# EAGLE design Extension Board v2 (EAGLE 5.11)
OC_FARNELL: 2065963

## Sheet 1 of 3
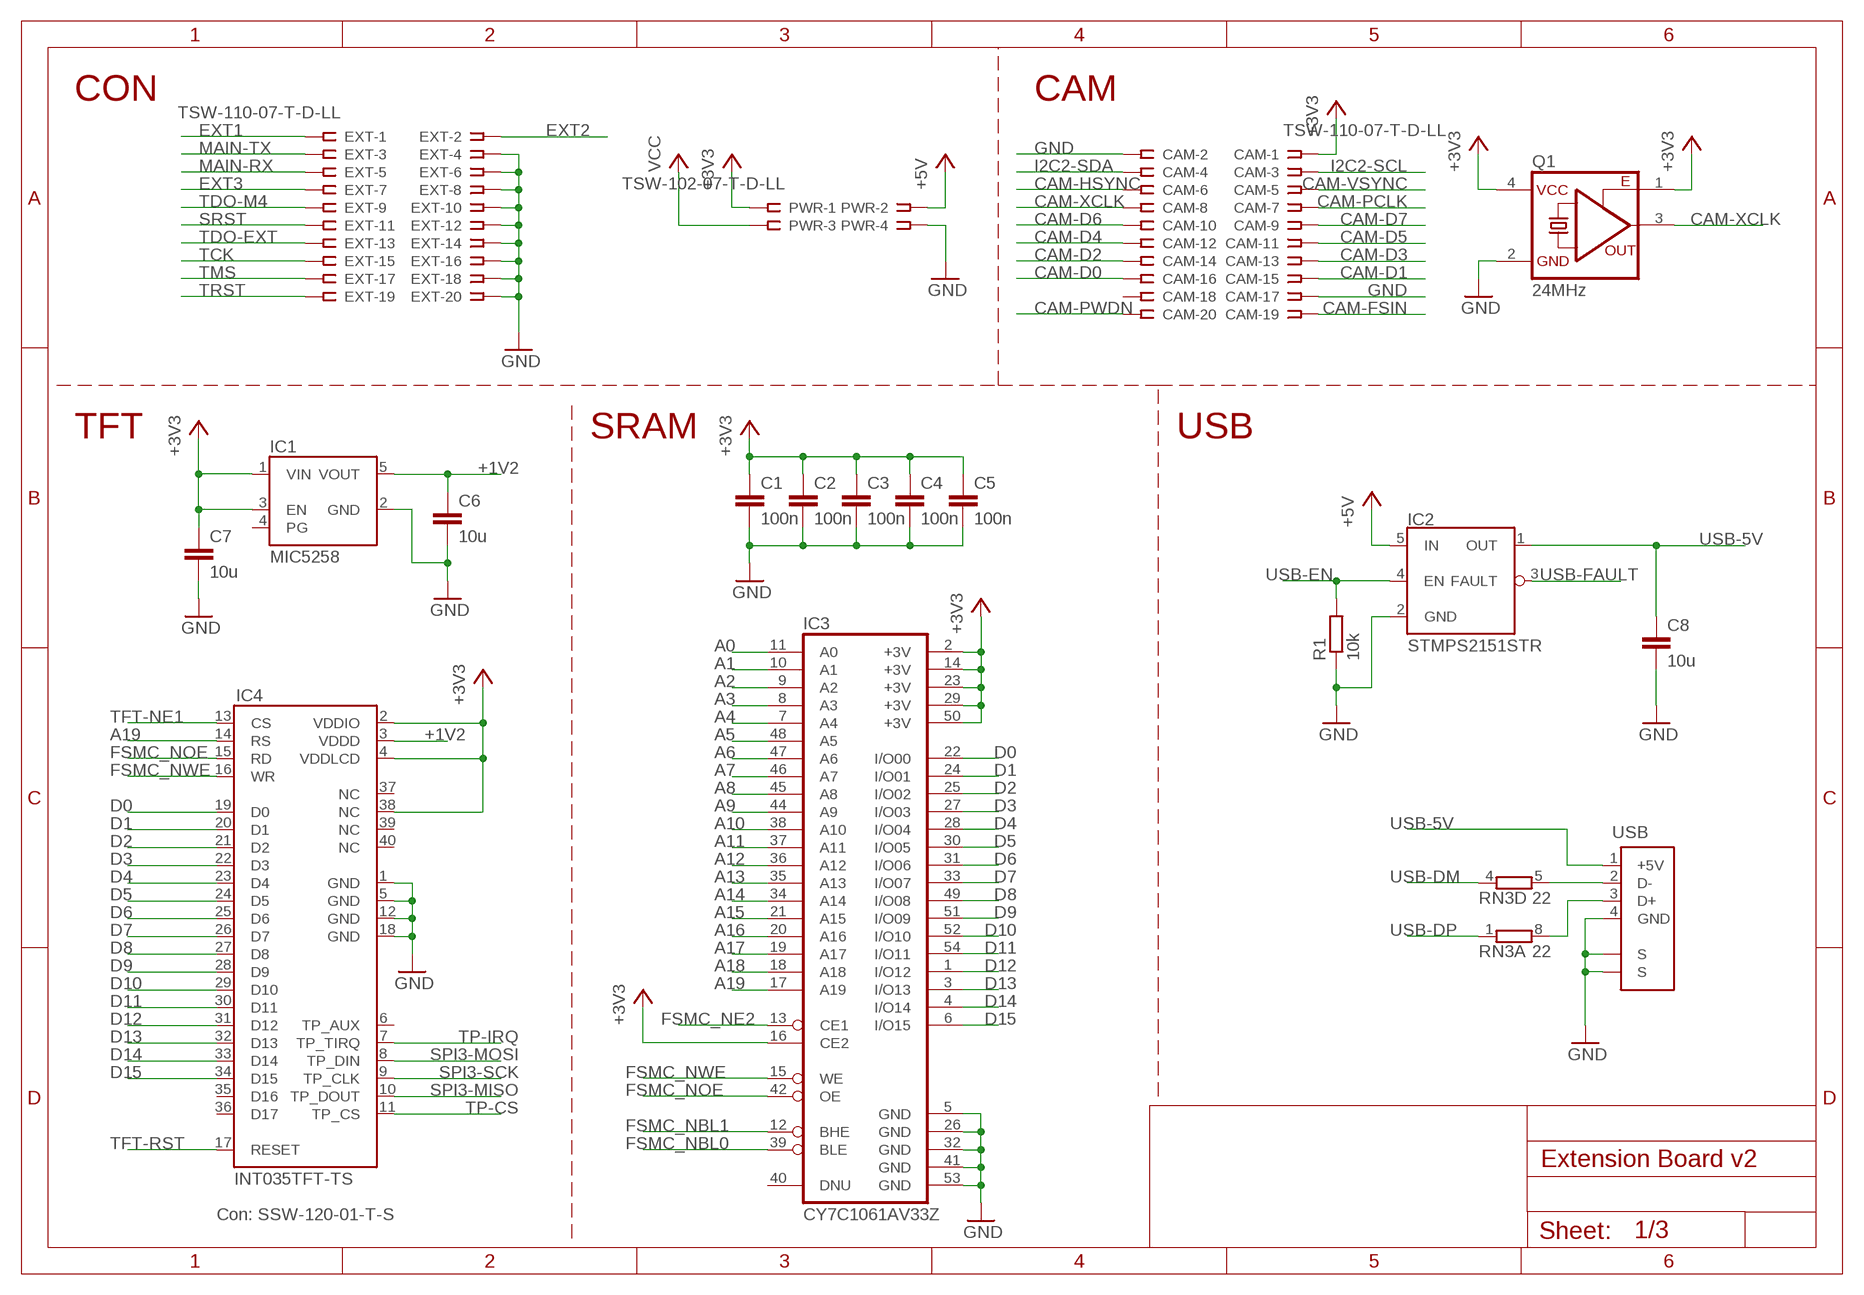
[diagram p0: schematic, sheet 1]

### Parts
C1  100n  C-EUC0805  [C0805]
C2  100n  C-EUC0805  [C0805]
C3  100n  C-EUC0805  [C0805]
C4  100n  C-EUC0805  [C0805]
C5  100n  C-EUC0805  [C0805]
C6  10u  C-EUC0805  [C0805]
C7  10u  C-EUC0805  [C0805]
C8  10u  C-EUC0805  [C0805]
CAM  TSW-110-07-T-D-LL  SSW-110-02-S-D  [SSW-110-02-S-D]
EXT  TSW-110-07-T-D-LL  SSW-110-02-S-D  [SSW-110-02-S-D]
IC1  MIC5258  LDO-EN-PG  [SOT23-5]
IC2  STMPS2151STR  [SOT23-5]
IC3  CY7C1061AV33Z  [TSOPII-54]
IC4  INT035TFT-TS  [INT035TFT-TS]
PWR  TSW-102-07-T-D-LL  SSW-102-02-S-D  [SSW-102-02-S-D]
Q1  24MHz  OSCI8W  [CRYSTAL-8W]
R1  10k  R-EU_R0805  [R0805]
RN3  22  4R-NCAY16  [CAY16]
USB  USBA  [USB-A-S-RA-TSMT]

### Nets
+1V2: C6.1 IC1.5(VOUT) IC4.3(VDDD)
+3V3: C1.1 C2.1 C3.1 C4.1 C5.1 C7.1 CAM.1 IC1.1(VIN) IC1.3(EN) IC3.2(+3V) IC3.14(+3V) IC3.16(CE2) IC3.23(+3V) IC3.29(+3V) IC3.50(+3V) IC4.2(VDDIO) IC4.4(VDDLCD) IC4.38(NC) PWR.1 Q1.1(OE) Q1.4(VCC) ; also sheet 3
+5V: IC2.5(IN) PWR.2 ; also sheet 2
A0: IC3.11(A0) ; also sheet 3
A1: IC3.10(A1) ; also sheet 3
A2: IC3.9(A2) ; also sheet 3
A3: IC3.8(A3) ; also sheet 3
A4: IC3.7(A4) ; also sheet 3
A5: IC3.48(A5) ; also sheet 3
A6: IC3.47(A6) ; also sheet 3
A7: IC3.46(A7) ; also sheet 3
A8: IC3.45(A8) ; also sheet 3
A9: IC3.44(A9) ; also sheet 3
A10: IC3.38(A10) ; also sheet 3
A11: IC3.37(A11) ; also sheet 3
A12: IC3.36(A12) ; also sheet 3
A13: IC3.35(A13) ; also sheet 3
A14: IC3.34(A14) ; also sheet 3
A15: IC3.21(A15) ; also sheet 3
A16: IC3.20(A16) ; also sheet 3
A17: IC3.19(A17) ; also sheet 3
A18: IC3.18(A18) ; also sheet 3
A19: IC3.17(A19) IC4.14(RS) ; also sheet 3
CAM-D0: CAM.16 ; also sheet 3
CAM-D1: CAM.15 ; also sheet 3
CAM-D2: CAM.14 ; also sheet 3
CAM-D3: CAM.13 ; also sheet 3
CAM-D4: CAM.12 ; also sheet 3
CAM-D5: CAM.11 ; also sheet 3
CAM-D6: CAM.10 ; also sheet 3
CAM-D7: CAM.9 ; also sheet 3
CAM-FSIN: CAM.19 ; also sheet 3
CAM-HSYNC: CAM.6 ; also sheet 3
CAM-PCLK: CAM.7 ; also sheet 3
CAM-PWDN: CAM.20 ; also sheet 3
CAM-VSYNC: CAM.5 ; also sheet 3
CAM-XCLK: CAM.8 Q1.3(FO)
D0: IC3.22(I/O00) IC4.19(D0) ; also sheet 3
D1: IC3.24(I/O01) IC4.20(D1) ; also sheet 3
D2: IC3.25(I/O02) IC4.21(D2) ; also sheet 3
D3: IC3.27(I/O03) IC4.22(D3) ; also sheet 3
D4: IC3.28(I/O04) IC4.23(D4) ; also sheet 3
D5: IC3.30(I/O05) IC4.24(D5) ; also sheet 3
D6: IC3.31(I/O06) IC4.25(D6) ; also sheet 3
D7: IC3.33(I/O07) IC4.26(D7) ; also sheet 3
D8: IC3.49(I/O08) IC4.27(D8) ; also sheet 3
D9: IC3.51(I/O09) IC4.28(D9) ; also sheet 3
D10: IC3.52(I/O10) IC4.29(D10) ; also sheet 3
D11: IC3.54(I/O11) IC4.30(D11) ; also sheet 3
D12: IC3.1(I/O12) IC4.31(D12) ; also sheet 3
D13: IC3.3(I/O13) IC4.32(D13) ; also sheet 3
D14: IC3.4(I/O14) IC4.33(D14) ; also sheet 3
D15: IC3.6(I/O15) IC4.34(D15) ; also sheet 3
EXT1: EXT.1 ; also sheet 3
EXT2: EXT.2 ; also sheet 3
EXT3: EXT.7 ; also sheet 3
FSMC_NBL0: IC3.39(BLE) ; also sheet 3
FSMC_NBL1: IC3.12(BHE) ; also sheet 3
FSMC_NE2: IC3.13(CE1) ; also sheet 3
FSMC_NOE: IC3.42(OE) IC4.15(RD) ; also sheet 3
FSMC_NWE: IC3.15(WE) IC4.16(WR) ; also sheet 3
GND: C1.2 C2.2 C3.2 C4.2 C5.2 C6.2 C7.2 C8.2 CAM.2 CAM.17 EXT.4 EXT.6 EXT.8 EXT.10 EXT.12 EXT.14 EXT.16 EXT.18 EXT.20 IC1.2(GND) IC2.2(GND) IC3.5(GND) IC3.26(GND) IC3.32(GND) IC3.41(GND) IC3.53(GND) IC4.1(GND) IC4.5(GND) IC4.12(GND) IC4.18(GND) PWR.4 Q1.2(GND) R1.1 USB.4(GND) USB.SHIELD@1(S) USB.SHIELD@2(S) ; also sheet 2,3
I2C2-SCL: CAM.3 ; also sheet 3
I2C2-SDA: CAM.4 ; also sheet 3
MAIN-RX: EXT.5 ; also sheet 3
MAIN-TX: EXT.3 ; also sheet 3
N$2: RN3.5 USB.2(D-)
N$3: RN3.8 USB.3(D+)
SPI3-MISO: IC4.10(TP_DOUT) ; also sheet 3
SPI3-MOSI: IC4.8(TP_DIN) ; also sheet 2,3
SPI3-SCK: IC4.9(TP_CLK) ; also sheet 2,3
SRST: EXT.11 ; also sheet 3
TCK: EXT.15 ; also sheet 3
TDO-EXT: EXT.13 ; also sheet 3
TDO-M4: EXT.9 ; also sheet 3
TFT-NE1: IC4.13(CS) ; also sheet 3
TFT-RST: IC4.17(RESET) ; also sheet 3
TMS: EXT.17 ; also sheet 3
TP-CS: IC4.11(TP_CS) ; also sheet 3
TP-IRQ: IC4.7(TP_TIRQ) ; also sheet 3
TRST: EXT.19 ; also sheet 3
USB-5V: C8.1 IC2.1(OUT) USB.1(+5V)
USB-DM: RN3.4 ; also sheet 3
USB-DP: RN3.1 ; also sheet 3
USB-EN: IC2.4(EN) R1.2 ; also sheet 3
USB-FAULT: IC2.3(FAULT) ; also sheet 3
VCC: PWR.3
Unconnected: CAM.18 IC1.4(PG) IC3.40(DNU) IC4.6(TP_AUX) IC4.35(D16) IC4.36(D17) IC4.37(NC) IC4.39(NC) IC4.40(NC) RN3.2 RN3.3 RN3.6 RN3.7

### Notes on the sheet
- CON | CAM
- TFT | SRAM | USB
- Con: SSW-120-01-T-S

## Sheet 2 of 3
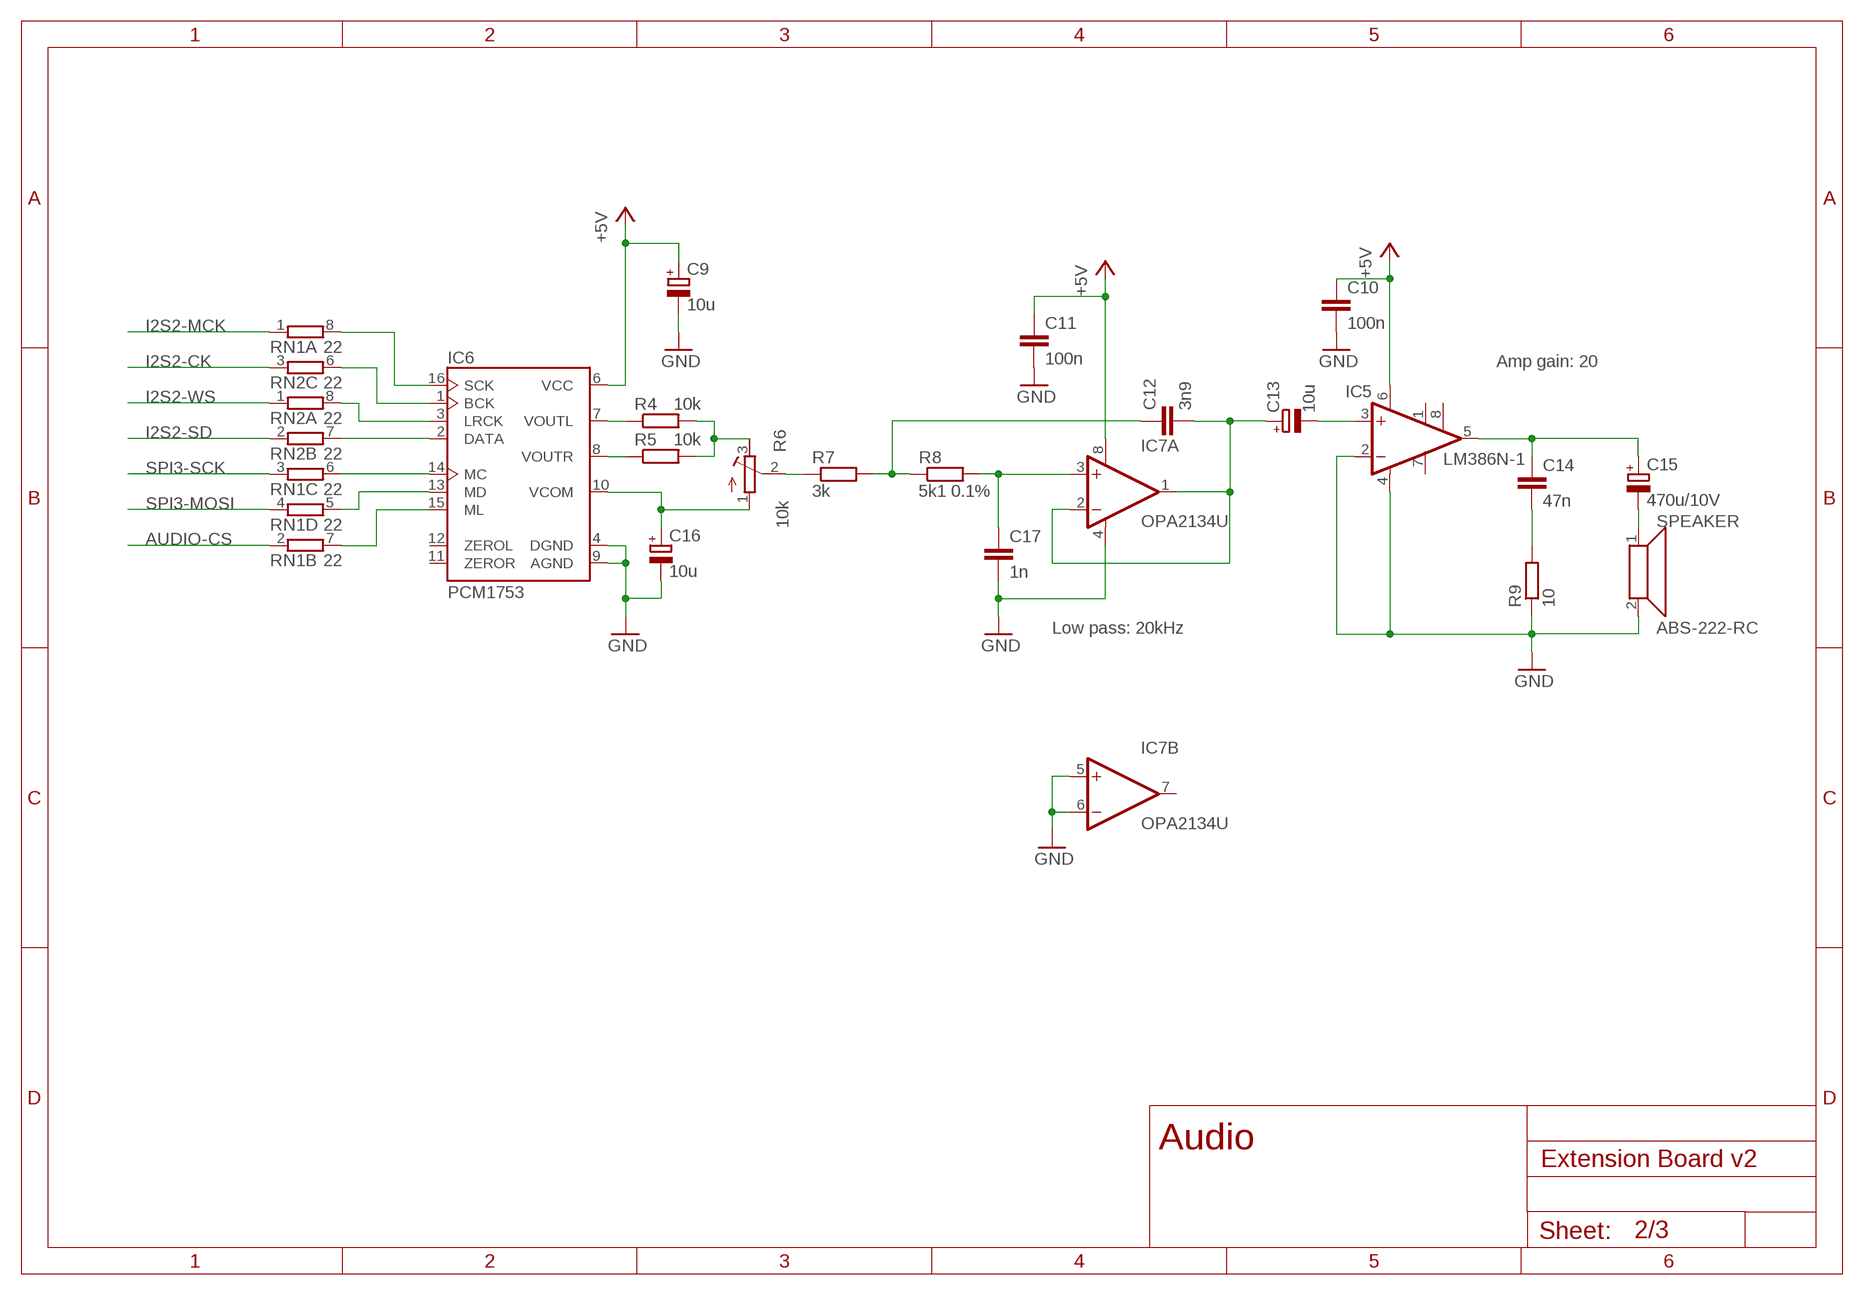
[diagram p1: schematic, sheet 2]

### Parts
C9  10u  CPOL-EUC  [PANASONIC_C]
C10  100n  C-EUC0805  [C0805]
C11  100n  C-EUC0805  [C0805]
C12  3n9  C-EUC0805  [C0805]
C13  10u  CPOL-EUC  [PANASONIC_C]
C14  47n  C-EUC0805  [C0805]
C15  470u/10V  CPOL-EUD  [PANASONIC_D]
C16  10u  CPOL-EUC  [PANASONIC_C]
C17  1n  C-EUC0805  [C0805]
IC5  LM386N-1  [DIL08]
IC6  PCM1753  [SSOP16]
IC7  OPA2134U  [SO08]
R4  10k  R-EU_R0805  [R0805]
R5  10k  R-EU_R0805  [R0805]
R6  10k  R-TRIMM64P  [RTRIM64P]
R7  3k  R-EU_R0805  [R0805]
R8  5k1 0.1%  R-EU_R0805  [R0805]
R9  10  R-EU_R0805  [R0805]
RN1  22  4R-NCAY16  [CAY16]
RN2  22  4R-NCAY16  [CAY16]
SPEAKER  ABS-222-RC  SPEAKERB  [ABS-222]

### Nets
+5V: C9.+ C10.1 C11.1 IC5.6(VS) IC6.6(VCC) IC7.8(A:V+) ; also sheet 1
AUDIO-CS: RN1.2 ; also sheet 3
GND: C9.- C10.2 C11.2 C16.- C17.2 IC5.2(-IN) IC5.4(GND) IC6.4(DGND) IC6.9(AGND) IC7.4(A:V-) IC7.5(B:+IN) IC7.6(B:-IN) R9.1 SPEAKER.2 ; also sheet 1,3
I2S2-CK: RN2.3 ; also sheet 3
I2S2-MCK: RN1.1 ; also sheet 3
I2S2-SD: RN2.2 ; also sheet 3
I2S2-WS: RN2.1 ; also sheet 3
N$1: R6.2(S) R7.1
N$4: IC6.2(DATA) RN2.7
N$6: IC6.3(LRCK) RN2.8
N$7: IC6.1(BCK) RN2.6
N$8: IC6.16(SCK) RN1.8
N$9: C14.1 C15.+ IC5.5(OUT)
N$10: C14.2 R9.2
N$11: C15.- SPEAKER.1
N$13: IC6.14(MC) RN1.6
N$14: IC6.13(MD) RN1.5
N$15: IC6.15(ML) RN1.7
N$16: IC6.7(VOUTL) R4.1
N$17: C12.1 R7.2 R8.1
N$19: C13.- IC5.3(+IN)
N$21: C16.+ IC6.10(VCOM) R6.1(E)
N$22: C17.1 IC7.3(A:+IN) R8.2
N$24: C12.2 C13.+ IC7.1(A:OUT) IC7.2(A:-IN)
N$25: IC6.8(VOUTR) R5.1
N$37: R4.2 R5.2 R6.3(A)
SPI3-MOSI: RN1.4 ; also sheet 1,3
SPI3-SCK: RN1.3 ; also sheet 1,3
Unconnected: IC5.1(GAIN) IC5.7(BYPASS) IC5.8(GAIN) IC6.11(ZEROR) IC6.12(ZEROL) IC7.7(B:OUT) RN2.4 RN2.5

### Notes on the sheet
- Amp gain: 20
- Low pass: 20kHz
- Audio

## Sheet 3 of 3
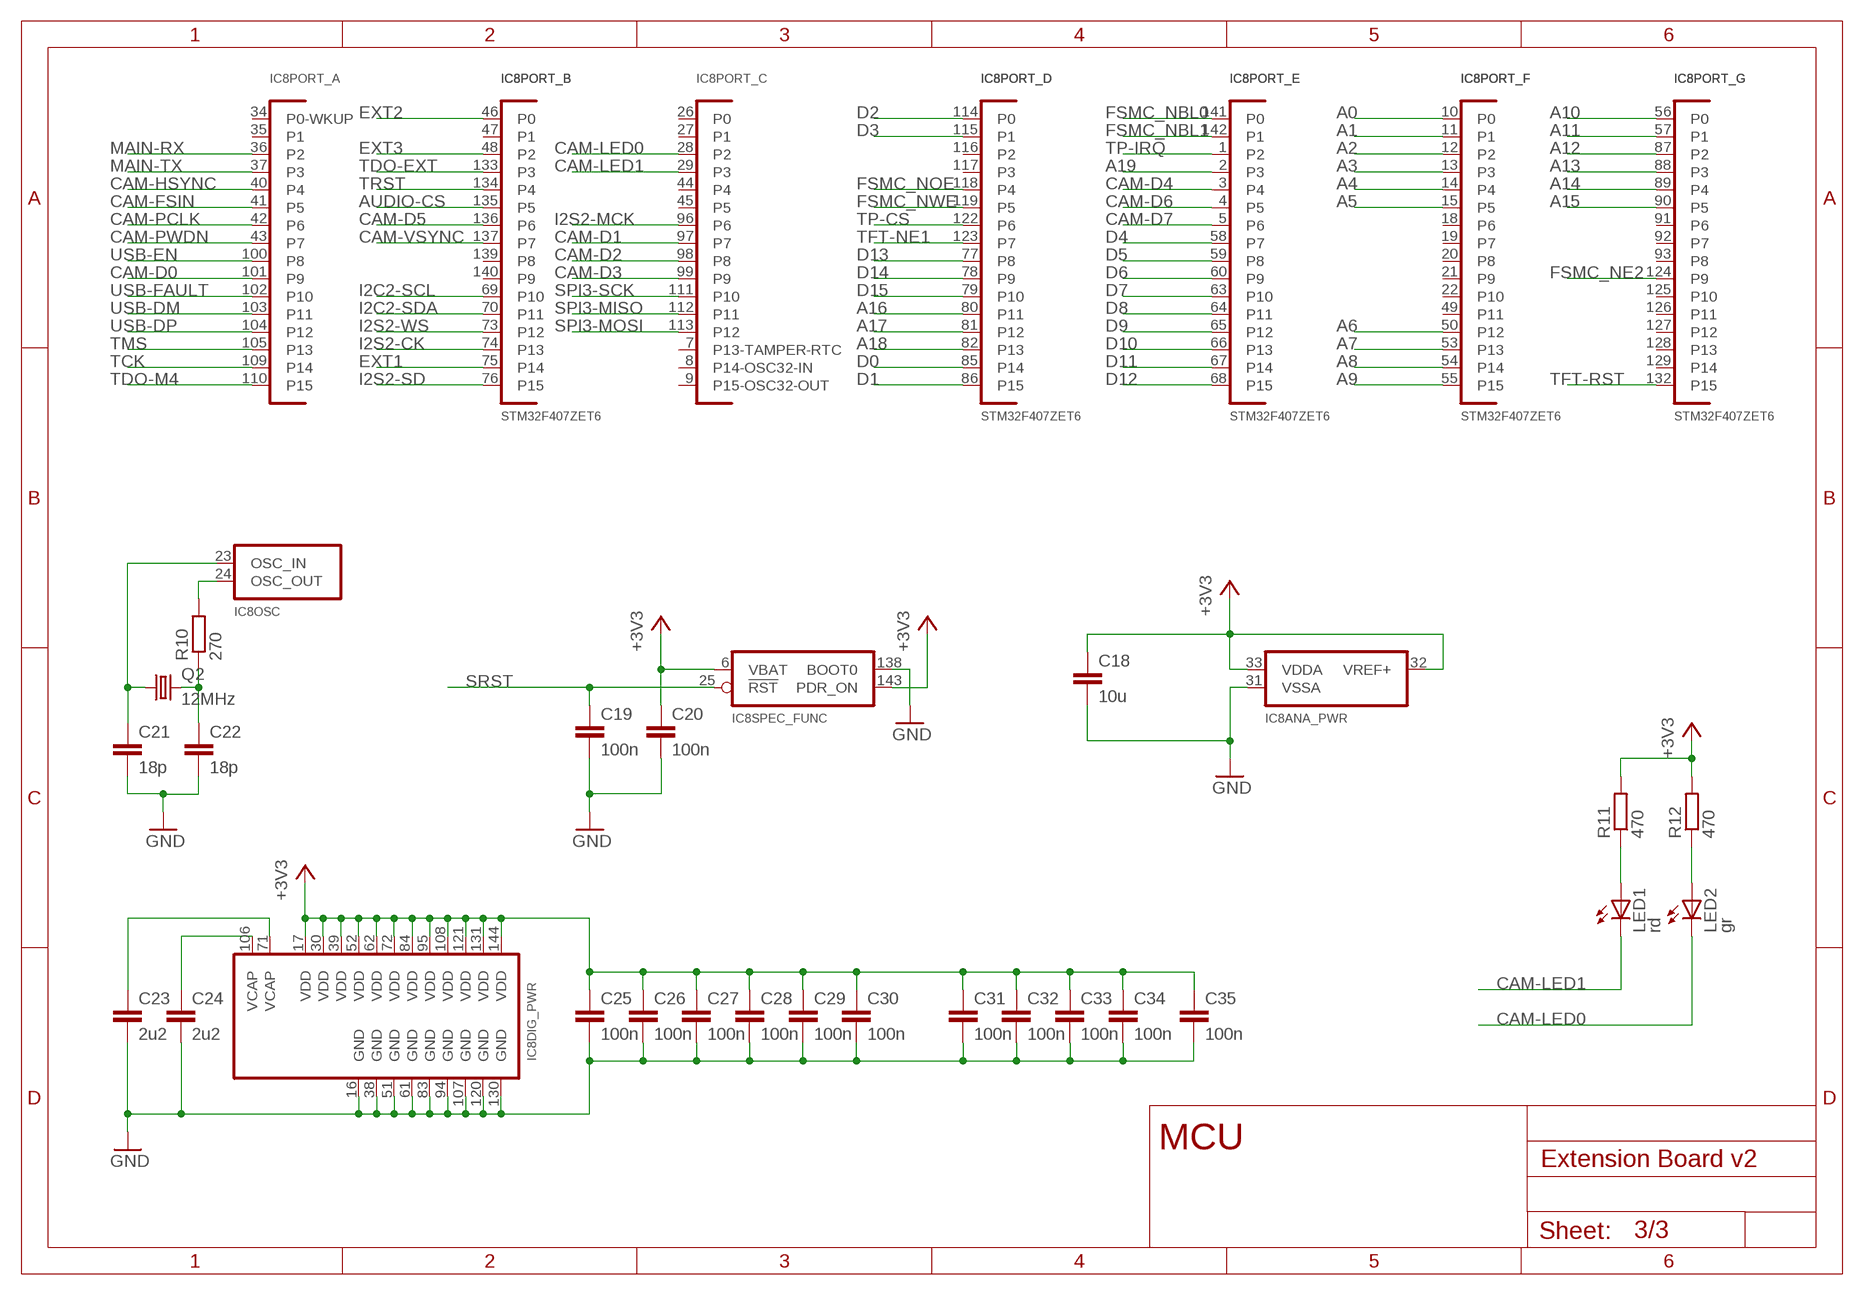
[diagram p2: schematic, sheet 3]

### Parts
C18  10u  C-EUC0805  [C0805]
C19  100n  C-EUC0805  [C0805]
C20  100n  C-EUC0805  [C0805]
C21  18p  C-EUC0805  [C0805]
C22  18p  C-EUC0805  [C0805]
C23  2u2  C-EUC0805  [C0805]
C24  2u2  C-EUC0805  [C0805]
C25  100n  C-EUC0805  [C0805]
C26  100n  C-EUC0805  [C0805]
C27  100n  C-EUC0805  [C0805]
C28  100n  C-EUC0805  [C0805]
C29  100n  C-EUC0805  [C0805]
C30  100n  C-EUC0805  [C0805]
C31  100n  C-EUC0805  [C0805]
C32  100n  C-EUC0805  [C0805]
C33  100n  C-EUC0805  [C0805]
C34  100n  C-EUC0805  [C0805]
C35  100n  C-EUC0805  [C0805]
IC8  STM32F407ZET6  STM32F40_Z  [SQFP-S-20X20-144]
LED1  rd  LEDCHIP-LED0805  [CHIP-LED0805]
LED2  gr  LEDCHIP-LED0805  [CHIP-LED0805]
Q2  12MHz  CRYSTAL7A  [CRYSTAL-7A]
R10  270  R-EU_R0805  [R0805]
R11  470  R-EU_R0805  [R0805]
R12  470  R-EU_R0805  [R0805]

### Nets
+3V3: C18.1 C20.1 C25.1 C26.1 C27.1 C28.1 C29.1 C30.1 C31.1 C32.1 C33.1 C34.1 C35.1 IC8.6(SPEC_FUNC:VBAT) IC8.17(DIG_PWR:VDD) IC8.30(DIG_PWR:VDD) IC8.32(ANA_PWR:VREF+) IC8.33(ANA_PWR:VDDA) IC8.39(DIG_PWR:VDD) IC8.52(DIG_PWR:VDD) IC8.62(DIG_PWR:VDD) IC8.72(DIG_PWR:VDD) IC8.84(DIG_PWR:VDD) IC8.95(DIG_PWR:VDD) IC8.108(DIG_PWR:VDD) IC8.121(DIG_PWR:VDD) IC8.131(DIG_PWR:VDD) IC8.143(SPEC_FUNC:PDR_ON) IC8.144(DIG_PWR:VDD) R11.2 R12.2 ; also sheet 1
A0: IC8.10(PORT_F:P0) ; also sheet 1
A1: IC8.11(PORT_F:P1) ; also sheet 1
A2: IC8.12(PORT_F:P2) ; also sheet 1
A3: IC8.13(PORT_F:P3) ; also sheet 1
A4: IC8.14(PORT_F:P4) ; also sheet 1
A5: IC8.15(PORT_F:P5) ; also sheet 1
A6: IC8.50(PORT_F:P12) ; also sheet 1
A7: IC8.53(PORT_F:P13) ; also sheet 1
A8: IC8.54(PORT_F:P14) ; also sheet 1
A9: IC8.55(PORT_F:P15) ; also sheet 1
A10: IC8.56(PORT_G:P0) ; also sheet 1
A11: IC8.57(PORT_G:P1) ; also sheet 1
A12: IC8.87(PORT_G:P2) ; also sheet 1
A13: IC8.88(PORT_G:P3) ; also sheet 1
A14: IC8.89(PORT_G:P4) ; also sheet 1
A15: IC8.90(PORT_G:P5) ; also sheet 1
A16: IC8.80(PORT_D:P11) ; also sheet 1
A17: IC8.81(PORT_D:P12) ; also sheet 1
A18: IC8.82(PORT_D:P13) ; also sheet 1
A19: IC8.2(PORT_E:P3) ; also sheet 1
AUDIO-CS: IC8.135(PORT_B:P5) ; also sheet 2
CAM-D0: IC8.101(PORT_A:P9) ; also sheet 1
CAM-D1: IC8.97(PORT_C:P7) ; also sheet 1
CAM-D2: IC8.98(PORT_C:P8) ; also sheet 1
CAM-D3: IC8.99(PORT_C:P9) ; also sheet 1
CAM-D4: IC8.3(PORT_E:P4) ; also sheet 1
CAM-D5: IC8.136(PORT_B:P6) ; also sheet 1
CAM-D6: IC8.4(PORT_E:P5) ; also sheet 1
CAM-D7: IC8.5(PORT_E:P6) ; also sheet 1
CAM-FSIN: IC8.41(PORT_A:P5) ; also sheet 1
CAM-HSYNC: IC8.40(PORT_A:P4) ; also sheet 1
CAM-LED0: IC8.28(PORT_C:P2) LED2.C
CAM-LED1: IC8.29(PORT_C:P3) LED1.C
CAM-PCLK: IC8.42(PORT_A:P6) ; also sheet 1
CAM-PWDN: IC8.43(PORT_A:P7) ; also sheet 1
CAM-VSYNC: IC8.137(PORT_B:P7) ; also sheet 1
D0: IC8.85(PORT_D:P14) ; also sheet 1
D1: IC8.86(PORT_D:P15) ; also sheet 1
D2: IC8.114(PORT_D:P0) ; also sheet 1
D3: IC8.115(PORT_D:P1) ; also sheet 1
D4: IC8.58(PORT_E:P7) ; also sheet 1
D5: IC8.59(PORT_E:P8) ; also sheet 1
D6: IC8.60(PORT_E:P9) ; also sheet 1
D7: IC8.63(PORT_E:P10) ; also sheet 1
D8: IC8.64(PORT_E:P11) ; also sheet 1
D9: IC8.65(PORT_E:P12) ; also sheet 1
D10: IC8.66(PORT_E:P13) ; also sheet 1
D11: IC8.67(PORT_E:P14) ; also sheet 1
D12: IC8.68(PORT_E:P15) ; also sheet 1
D13: IC8.77(PORT_D:P8) ; also sheet 1
D14: IC8.78(PORT_D:P9) ; also sheet 1
D15: IC8.79(PORT_D:P10) ; also sheet 1
EXT1: IC8.75(PORT_B:P14) ; also sheet 1
EXT2: IC8.46(PORT_B:P0) ; also sheet 1
EXT3: IC8.48(PORT_B:P2) ; also sheet 1
FSMC_NBL0: IC8.141(PORT_E:P0) ; also sheet 1
FSMC_NBL1: IC8.142(PORT_E:P1) ; also sheet 1
FSMC_NE2: IC8.124(PORT_G:P9) ; also sheet 1
FSMC_NOE: IC8.118(PORT_D:P4) ; also sheet 1
FSMC_NWE: IC8.119(PORT_D:P5) ; also sheet 1
GND: C18.2 C19.2 C20.2 C21.2 C22.2 C23.2 C24.2 C25.2 C26.2 C27.2 C28.2 C29.2 C30.2 C31.2 C32.2 C33.2 C34.2 C35.2 IC8.16(DIG_PWR:GND) IC8.31(ANA_PWR:VSSA) IC8.38(DIG_PWR:GND) IC8.51(DIG_PWR:GND) IC8.61(DIG_PWR:GND) IC8.83(DIG_PWR:GND) IC8.94(DIG_PWR:GND) IC8.107(DIG_PWR:GND) IC8.120(DIG_PWR:GND) IC8.130(DIG_PWR:GND) IC8.138(SPEC_FUNC:BOOT0) ; also sheet 1,2
I2C2-SCL: IC8.69(PORT_B:P10) ; also sheet 1
I2C2-SDA: IC8.70(PORT_B:P11) ; also sheet 1
I2S2-CK: IC8.74(PORT_B:P13) ; also sheet 2
I2S2-MCK: IC8.96(PORT_C:P6) ; also sheet 2
I2S2-SD: IC8.76(PORT_B:P15) ; also sheet 2
I2S2-WS: IC8.73(PORT_B:P12) ; also sheet 2
MAIN-RX: IC8.36(PORT_A:P2) ; also sheet 1
MAIN-TX: IC8.37(PORT_A:P3) ; also sheet 1
N$27: C24.1 IC8.106(DIG_PWR:VCAP)
N$28: C23.1 IC8.71(DIG_PWR:VCAP)
N$31: IC8.24(OSC:OSC_OUT) R10.2
N$32: C21.1 IC8.23(OSC:OSC_IN) Q2.1
N$33: C22.1 Q2.2 R10.1
N$35: LED2.A R12.1
N$36: LED1.A R11.1
SPI3-MISO: IC8.112(PORT_C:P11) ; also sheet 1
SPI3-MOSI: IC8.113(PORT_C:P12) ; also sheet 1,2
SPI3-SCK: IC8.111(PORT_C:P10) ; also sheet 1,2
SRST: C19.1 IC8.25(SPEC_FUNC:!RST) ; also sheet 1
TCK: IC8.109(PORT_A:P14) ; also sheet 1
TDO-EXT: IC8.133(PORT_B:P3) ; also sheet 1
TDO-M4: IC8.110(PORT_A:P15) ; also sheet 1
TFT-NE1: IC8.123(PORT_D:P7) ; also sheet 1
TFT-RST: IC8.132(PORT_G:P15) ; also sheet 1
TMS: IC8.105(PORT_A:P13) ; also sheet 1
TP-CS: IC8.122(PORT_D:P6) ; also sheet 1
TP-IRQ: IC8.1(PORT_E:P2) ; also sheet 1
TRST: IC8.134(PORT_B:P4) ; also sheet 1
USB-DM: IC8.103(PORT_A:P11) ; also sheet 1
USB-DP: IC8.104(PORT_A:P12) ; also sheet 1
USB-EN: IC8.100(PORT_A:P8) ; also sheet 1
USB-FAULT: IC8.102(PORT_A:P10) ; also sheet 1
Unconnected: IC8.7(PORT_C:P13-TAMPER-RTC) IC8.8(PORT_C:P14-OSC32-IN) IC8.9(PORT_C:P15-OSC32-OUT) IC8.18(PORT_F:P6) IC8.19(PORT_F:P7) IC8.20(PORT_F:P8) IC8.21(PORT_F:P9) IC8.22(PORT_F:P10) IC8.26(PORT_C:P0) IC8.27(PORT_C:P1) IC8.34(PORT_A:P0-WKUP) IC8.35(PORT_A:P1) IC8.44(PORT_C:P4) IC8.45(PORT_C:P5) IC8.47(PORT_B:P1) IC8.49(PORT_F:P11) IC8.91(PORT_G:P6) IC8.92(PORT_G:P7) IC8.93(PORT_G:P8) IC8.116(PORT_D:P2) IC8.117(PORT_D:P3) IC8.125(PORT_G:P10) IC8.126(PORT_G:P11) IC8.127(PORT_G:P12) IC8.128(PORT_G:P13) IC8.129(PORT_G:P14) IC8.139(PORT_B:P8) IC8.140(PORT_B:P9)

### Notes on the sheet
- MCU

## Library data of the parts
C1-C8 C10-C12 C14 C17-C35 = rcl:C-EU: CAPACITOR, European symbol
C9 C13 C15 C16 = rcl:CPOL-EU: POLARIZED CAPACITOR, European symbol
CAM EXT = con-samtec:SSW-110-02-S-D: THROUGH-HOLE .025" SQ POST SOCKET Source: Samtec SSW.pdf; MPN: SSW-110-02-S-D; OC_FARNELL: unknown; OC_NEWARK: 11P9480
IC1 = Marvin:LDO-EN-PG
IC2 = Marvin:STMPS21
IC3 = Marvin:CY7C1061AV33Z: 1M x 16 Static RAM Source: CYPRESS cy7c1061av33_8.pdf
IC4 = Marvin:INT035TFT-TS: Displaytech INT035TFT-TS QVGA full color display with touch-screen
IC5 = linear:LM386?-*: Low Voltage Audio Power Amplifier Source: http://cache.national.com/ds/LM/LM386.pdf
IC6 = Marvin:PCM1753
IC7 = burr-brown:OPA2134: Operational Amplifier; MF: TEXAS INSTRUMENTS; MPN: OPA2134UA; OC_FARNELL: 1206935; OC_NEWARK: 35C1847
IC8 = Marvin:STM32F40_Z: 168 MHz, 192KB RAM, 1024 KB Flash
LED1 LED2 = led:LED: LED
PWR = con-samtec:SSW-102-02-S-D: THROUGH-HOLE .025" SQ POST SOCKET Source: Samtec SSW.pdf; MPN: SSW-102-02-S-D; OC_FARNELL: unknown; OC_NEWARK: 11P9349
Q1 = Marvin:OSCI
Q2 = Marvin:CRYSTAL
R1 R4 R5 R7-R12 = rcl:R-EU_: RESISTOR, European symbol
R6 = rcl:R-TRIMM: Trimm resistor
RN1-RN3 = resistor-dil:4R-N: Array Chip Resistor Source: RS Component / Phycomp; OC_FARNELL: unknown; OC_NEWARK: unknown
SPEAKER = Marvin:SPEAKER
USB = Marvin:USBA: Multicomp connector Farnell: 2112370

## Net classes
0 default: width 0.152 mm, clearance 0.152 mm

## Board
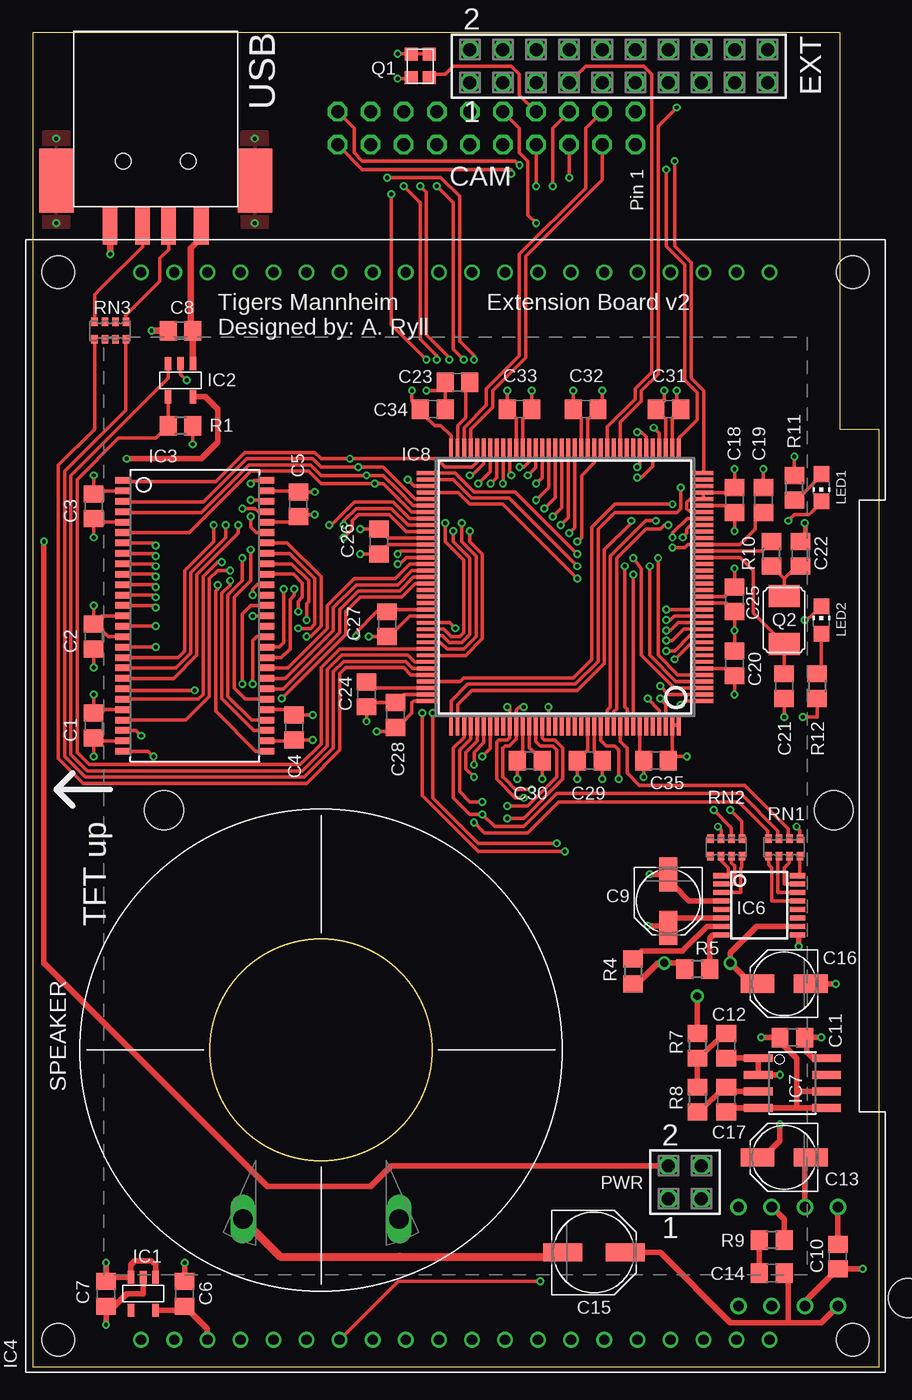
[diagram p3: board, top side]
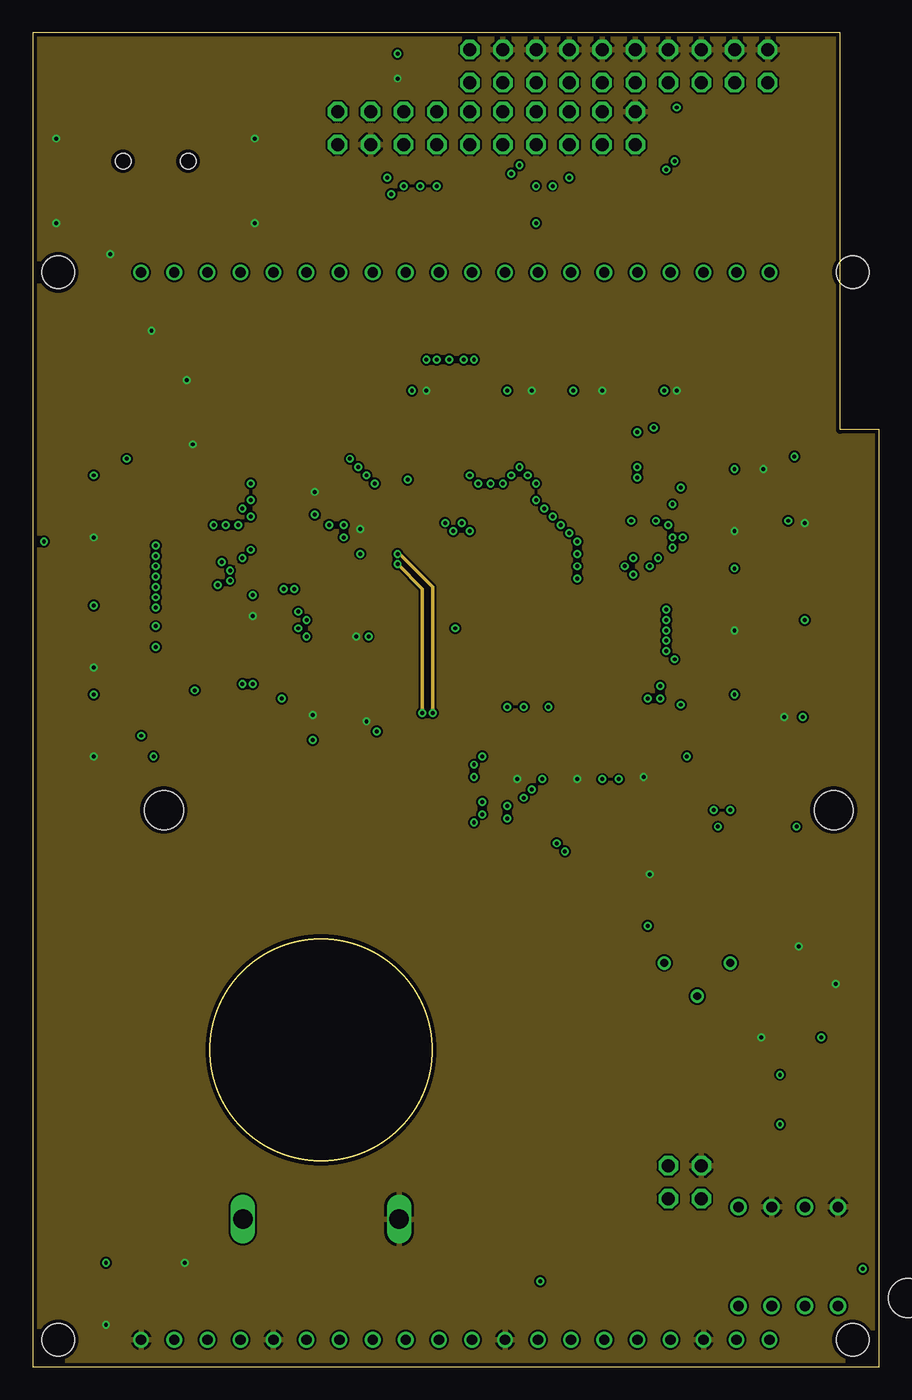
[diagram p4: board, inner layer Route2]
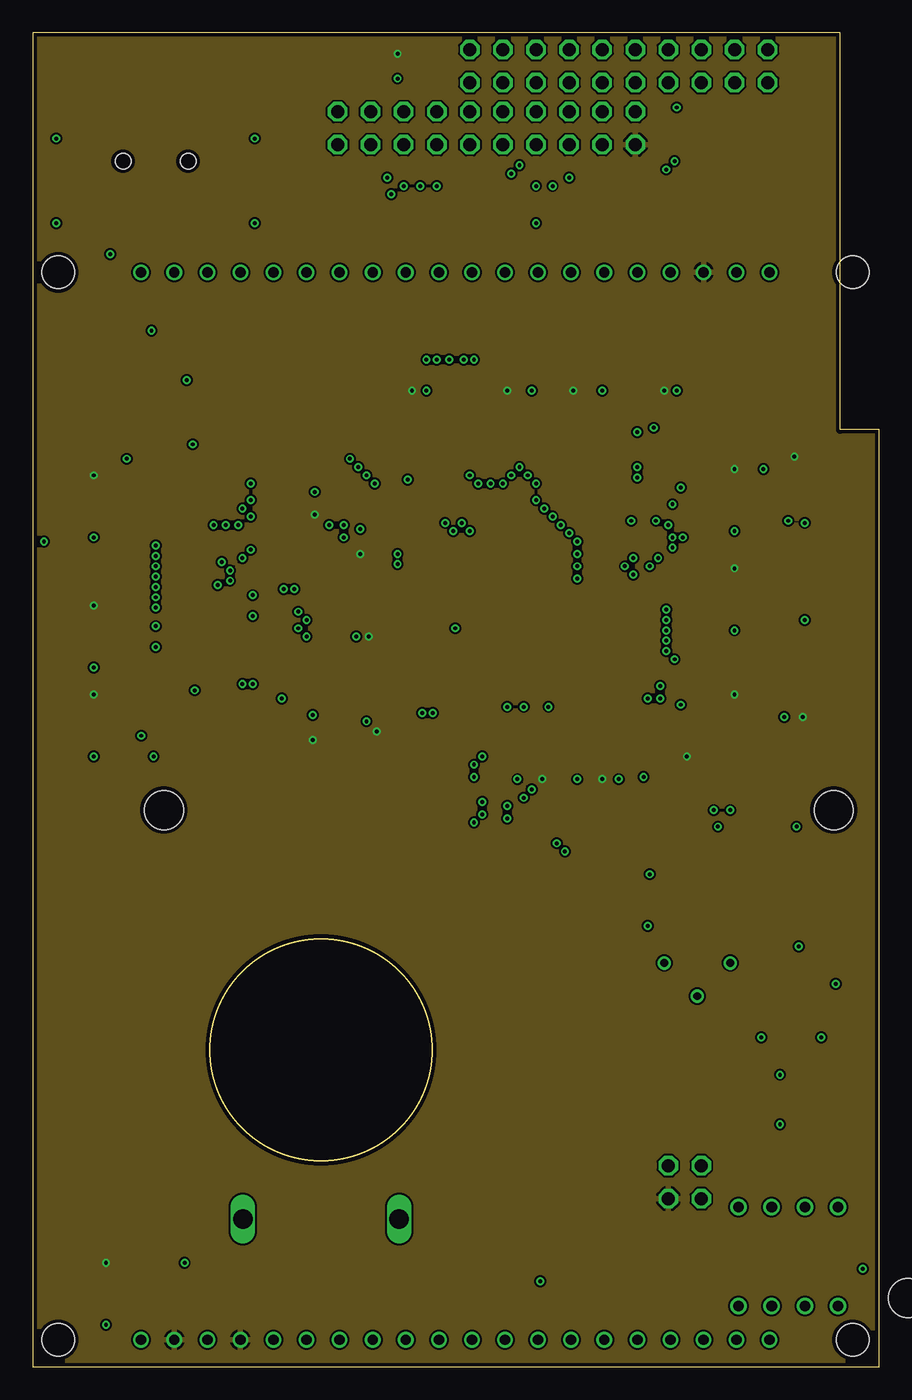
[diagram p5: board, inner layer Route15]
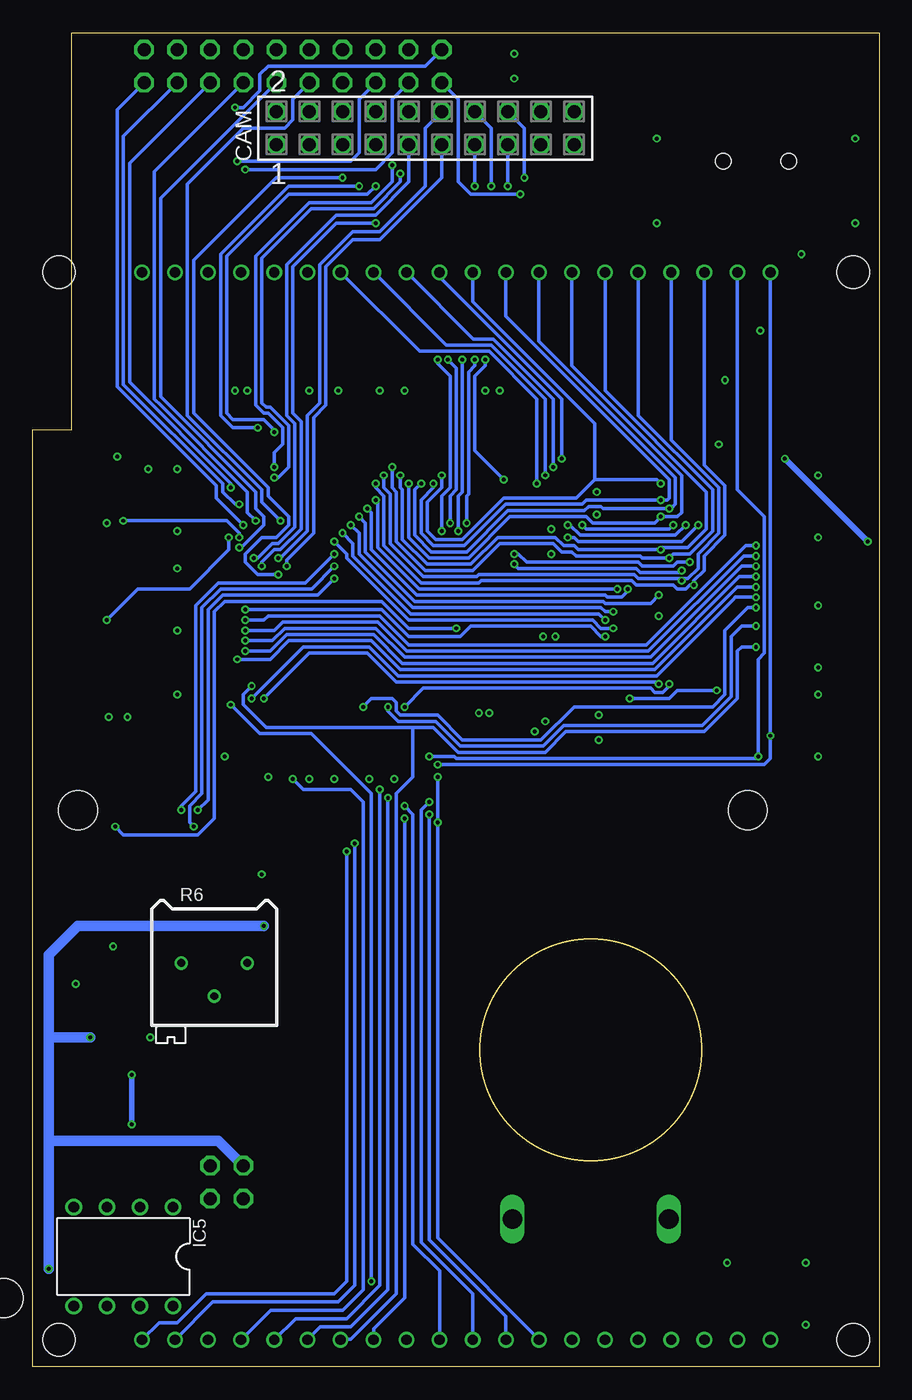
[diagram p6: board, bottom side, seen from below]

Size 65 x 102.5 mm. Coordinates in mm from the lower left corner, seen from the top.
Outline: 0,0 65,0 65,72 62,72 62,102.5 0,102.5 0,0
Copper layers (1+2*15+16): Top 0.035mm / dielectric 0.38mm / Route2 0.035mm / dielectric 0.71mm / Route15 0.035mm / dielectric 0.38mm / Bottom 0.035mm
Design rules "PCB-POOL Standard_ML4": minimum track width 0.15mm, minimum drill 0.3mm, track to track 0.15mm, track to pad 0.15mm, pad to pad 0.15mm, via to via 0.15mm, smd to smd 0.15mm, copper to edge 0.3mm, drill to drill 0.2mm, minimum pad ring 0.2mm, minimum via ring 0.15mm, stop-mask expansion 0.075mm, vias tented up to drill 0mil, thermal gap 0.2mm
Holes 3 mm at 61.52,42.77 10.09,42.77 67.23,5.3
tKeepout: area 7.1,39.8 to 13.1,45.8

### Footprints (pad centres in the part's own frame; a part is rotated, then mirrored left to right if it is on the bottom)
C0805 = smd 1.3 x 1.5: 1 -0.95,0; 2 0.95,0
PANASONIC_C = smd 2.6 x 1.4: + 2.05,0; - -2.05,0
PANASONIC_D = smd 3 x 1.4: + 2.4,0; - -2.4,0
SSW-110-02-S-D = drill 1 pad 1.5 octagon: 1 -11.43,-1.27; 2 -11.43,1.27; 3 -8.89,-1.27; 4 -8.89,1.27; 5 -6.35,-1.27; 6 -6.35,1.27; 7 -3.81,-1.27; 8 -3.81,1.27; 9 -1.27,-1.27; 10 -1.27,1.27; 11 1.27,-1.27; 12 1.27,1.27; 13 3.81,-1.27; 14 3.81,1.27; 15 6.35,-1.27; 16 6.35,1.27; 17 8.89,-1.27; 18 8.89,1.27; 19 11.43,-1.27; 20 11.43,1.27
SOT23-5 = smd 1.016 x 0.508: 1 -1.27,0.953; 2 -1.27,0; 3 -1.27,-0.953; 4 1.27,-0.953; 5 1.27,0.953
TSOPII-54 = smd 0.5 x 1.2: 1 -10.4,-5.502; 2 -9.6,-5.502; 3 -8.8,-5.502; 4 -8,-5.502; 5 -7.2,-5.502; 6 -6.4,-5.502; 7 -5.6,-5.502; 8 -4.8,-5.502; 9 -4,-5.502; 10 -3.2,-5.502; 11 -2.4,-5.502; 12 -1.6,-5.502; 13 -0.8,-5.502; 14 0,-5.502; 15 0.8,-5.502; 16 1.6,-5.502; 17 2.4,-5.502; 18 3.2,-5.502; 19 4,-5.502; 20 4.8,-5.502; 21 5.6,-5.502; 22 6.4,-5.502; 23 7.2,-5.502; 24 8,-5.502; 25 8.8,-5.502; 26 9.6,-5.502; 27 10.4,-5.502; 28 10.4,5.502; 29 9.6,5.502; 30 8.8,5.502; 31 8,5.502; 32 7.2,5.502; 33 6.4,5.502; 34 5.6,5.502; 35 4.8,5.502; 36 4,5.502; 37 3.2,5.502; 38 2.4,5.502; 39 1.6,5.502; 40 0.8,5.502; 41 0,5.502; 42 -0.8,5.502; 43 -1.6,5.502; 44 -2.4,5.502; 45 -3.2,5.502; 46 -4,5.502; 47 -4.8,5.502; 48 -5.6,5.502; 49 -6.4,5.502; 50 -7.2,5.502; 51 -8,5.502; 52 -8.8,5.502; 53 -9.6,5.502; 54 -10.4,5.502
INT035TFT-TS = drill 0.8 round: 1 -41,24.13; 2 -41,21.59; 3 -41,19.05; 4 -41,16.51; 5 -41,13.97; 6 -41,11.43; 7 -41,8.89; 8 -41,6.35; 9 -41,3.81; 10 -41,1.27; 11 -41,-1.27; 12 -41,-3.81; 13 -41,-6.35; 14 -41,-8.89; 15 -41,-11.43; 16 -41,-13.97; 17 -41,-16.51; 18 -41,-19.05; 19 -41,-21.59; 20 -41,-24.13; 21 41,24.13; 22 41,21.59; 23 41,19.05; 24 41,16.51; 25 41,13.97; 26 41,11.43; 27 41,8.89; 28 41,6.35; 29 41,3.81; 30 41,1.27; 31 41,-1.27; 32 41,-3.81; 33 41,-6.35; 34 41,-8.89; 35 41,-11.43; 36 41,-13.97; 37 41,-16.51; 38 41,-19.05; 39 41,-21.59; 40 41,-24.13 | hole 2.5: -41,30.5; 41,30.5; 41,-30.5; -41,-30.5
DIL08 = drill 0.813 pad 1.27 round: 1 -3.81,-3.81; 2 -1.27,-3.81; 3 1.27,-3.81; 4 3.81,-3.81; 5 3.81,3.81; 6 1.27,3.81; 7 -1.27,3.81; 8 -3.81,3.81
SSOP16 = smd 0.4 x 1.2: 1 -2.275,-2.925; 2 -1.625,-2.925; 3 -0.975,-2.925; 4 -0.325,-2.925; 5 0.325,-2.925; 6 0.975,-2.925; 7 1.625,-2.925; 8 2.275,-2.925; 9 2.275,2.925; 10 1.625,2.925; 11 0.975,2.925; 12 0.325,2.925; 13 -0.325,2.925; 14 -0.975,2.925; 15 -1.625,2.925; 16 -2.275,2.925
SO08 = smd 0.61 x 2.21: 1 -1.905,-2.616; 2 -0.635,-2.616; 3 0.635,-2.616; 4 1.905,-2.616; 5 1.905,2.616; 6 0.635,2.616; 7 -0.635,2.616; 8 -1.905,2.616
SQFP-S-20X20-144 = smd 0.3 x 1.6: 1 -8.75,-10.6; 2 -8.25,-10.6; 3 -7.75,-10.6; 4 -7.25,-10.6; 5 -6.75,-10.6; 6 -6.25,-10.6; 7 -5.75,-10.6; 8 -5.25,-10.6; 9 -4.75,-10.6; 10 -4.25,-10.6; 11 -3.75,-10.6; 12 -3.25,-10.6; 13 -2.75,-10.6; 14 -2.25,-10.6; 15 -1.75,-10.6; 16 -1.25,-10.6; 17 -0.75,-10.6; 18 -0.25,-10.6; 19 0.25,-10.6; 20 0.75,-10.6; 21 1.25,-10.6; 22 1.75,-10.6; 23 2.25,-10.6; 24 2.75,-10.6; 25 3.25,-10.6; 26 3.75,-10.6; 27 4.25,-10.6; 28 4.75,-10.6; 29 5.25,-10.6; 30 5.75,-10.6; 31 6.25,-10.6; 32 6.75,-10.6; 33 7.25,-10.6; 34 7.75,-10.6; 35 8.25,-10.6; 36 8.75,-10.6; 73 8.75,10.6; 74 8.25,10.6; 75 7.75,10.6; 76 7.25,10.6; 77 6.75,10.6; 78 6.25,10.6; 79 5.75,10.6; 80 5.25,10.6; 81 4.75,10.6; 82 4.25,10.6; 83 3.75,10.6; 84 3.25,10.6; 85 2.75,10.6; 86 2.25,10.6; 87 1.75,10.6; 88 1.25,10.6; 89 0.75,10.6; 90 0.25,10.6; 91 -0.25,10.6; 92 -0.75,10.6; 93 -1.25,10.6; 94 -1.75,10.6; 95 -2.25,10.6; 96 -2.75,10.6; 97 -3.25,10.6; 98 -3.75,10.6; 99 -4.25,10.6; 100 -4.75,10.6; 101 -5.25,10.6; 102 -5.75,10.6; 103 -6.25,10.6; 104 -6.75,10.6; 105 -7.25,10.6; 106 -7.75,10.6; 107 -8.25,10.6; 108 -8.75,10.6 | smd 1.6 x 0.3: 37 10.6,-8.75; 38 10.6,-8.25; 39 10.6,-7.75; 40 10.6,-7.25; 41 10.6,-6.75; 42 10.6,-6.25; 43 10.6,-5.75; 44 10.6,-5.25; 45 10.6,-4.75; 46 10.6,-4.25; 47 10.6,-3.75; 48 10.6,-3.25; 49 10.6,-2.75; 50 10.6,-2.25; 51 10.6,-1.75; 52 10.6,-1.25; 53 10.6,-0.75; 54 10.6,-0.25; 55 10.6,0.25; 56 10.6,0.75; 57 10.6,1.25; 58 10.6,1.75; 59 10.6,2.25; 60 10.6,2.75; 61 10.6,3.25; 62 10.6,3.75; 63 10.6,4.25; 64 10.6,4.75; 65 10.6,5.25; 66 10.6,5.75; 67 10.6,6.25; 68 10.6,6.75; 69 10.6,7.25; 70 10.6,7.75; 71 10.6,8.25; 72 10.6,8.75; 109 -10.6,8.75; 110 -10.6,8.25; 111 -10.6,7.75; 112 -10.6,7.25; 113 -10.6,6.75; 114 -10.6,6.25; 115 -10.6,5.75; 116 -10.6,5.25; 117 -10.6,4.75; 118 -10.6,4.25; 119 -10.6,3.75; 120 -10.6,3.25; 121 -10.6,2.75; 122 -10.6,2.25; 123 -10.6,1.75; 124 -10.6,1.25; 125 -10.6,0.75; 126 -10.6,0.25; 127 -10.6,-0.25; 128 -10.6,-0.75; 129 -10.6,-1.25; 130 -10.6,-1.75; 131 -10.6,-2.25; 132 -10.6,-2.75; 133 -10.6,-3.25; 134 -10.6,-3.75; 135 -10.6,-4.25; 136 -10.6,-4.75; 137 -10.6,-5.25; 138 -10.6,-5.75; 139 -10.6,-6.25; 140 -10.6,-6.75; 141 -10.6,-7.25; 142 -10.6,-7.75; 143 -10.6,-8.25; 144 -10.6,-8.75
CHIP-LED0805 = smd 1.2 x 1.2: A 0,-1.05; C 0,1.05
SSW-102-02-S-D = drill 1 pad 1.5 octagon: 1 -1.27,-1.27; 2 -1.27,1.27; 3 1.27,-1.27; 4 1.27,1.27
CRYSTAL-8W = smd 1 x 1: 1 -0.9,-0.7; 2 0.9,-0.7; 3 0.9,0.7; 4 -0.9,0.7
CRYSTAL-7A = smd 1.7 x 2.4: 1 -1.85,0; 2 1.85,0
R0805 = smd 1.3 x 1.5: 1 -0.95,0; 2 0.95,0
RTRIM64P = drill 0.61 round: 1 0,-2.54; 2 2.54,0; 3 0,2.54
CAY16 = smd 0.5 x 0.65: 1 -1.2,-0.675; 2 -0.4,-0.675; 3 0.4,-0.675; 4 1.2,-0.675; 5 1.2,0.675; 6 0.4,0.675; 7 -0.4,0.675; 8 -1.2,0.675
ABS-222 = drill 1.5 long: 1 -6,-13; 2 6,-13
USB-A-S-RA-TSMT = smd 1.12 x 2.88: 1 3.5,-4.96; 2 1,-4.96; 3 -1,-4.96; 4 -3.5,-4.96 | smd 2.65 x 4.9: SHIELD@1 -7.625,-1.5; SHIELD@2 7.625,-1.5 | hole 1.2: -2.5,0; 2.5,0

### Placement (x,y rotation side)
C1  4.69,49.28 270 top
C2  4.69,56.11 270 top
C3  4.69,66.11 270 top
C4  20.09,49.12 90 top
C5  20.4,66.27 90 top
C6  11.67,5.62 90 top
C7  5.64,5.62 270 top
C8  11.35,79.6 180 top
C9  48.82,35.78 270 top
C10  61.84,8.48 90 top
C11  58.34,25.31 180 top
C12  53.27,24.67 270 top
C13  57.71,16.1 180 top
C14  56.76,7.21 180 top
C15  43.11,8.8 0 top
C16  57.71,29.44 180 top
C17  53.27,20.55 270 top
C18  53.9,66.58 270 top
C19  56.12,66.58 90 top
C20  53.9,54.04 90 top
C21  57.71,52.3 270 top
C22  58.98,62.45 90 top
C23  32.63,75.63 180 top
C24  25.64,51.66 270 top
C25  53.9,58.96 270 top
C26  26.59,63.41 90 top
C27  27.23,57.06 90 top
C28  27.87,50.07 90 top
C29  42.79,46.58 180 top
C30  38.18,46.58 180 top
C31  48.82,73.57 0 top
C32  42.47,73.57 0 top
C33  37.39,73.57 0 top
C34  30.72,73.57 0 top
C35  47.87,46.58 180 top
CAM  34.85,95.16 0 bottom
EXT  45.01,99.92 0 top
IC1  8.5,5.62 270 top
IC2  11.35,75.79 270 top
IC3  12.47,57.69 270 top
IC4  32.47,43.09 90 top
IC5  58.03,8.48 180 bottom
IC6  55.81,35.47 270 top
IC7  58.34,21.81 270 top
IC8  40.88,59.92 90 top
LED1  60.57,67.53 180 top
LED2  60.57,57.38 0 top
PWR  50.09,14.2 0 top
Q1  29.77,99.92 270 top
Q2  57.71,57.38 90 top
R1  11.35,72.3 180 top
R4  46.12,30.39 270 top
R5  51.04,30.55 180 top
R6  51.04,31.02 270 bottom
R7  51.04,24.67 270 top
R8  51.04,20.55 270 top
R9  56.76,9.75 180 top
R10  56.76,62.45 90 top
R11  58.5,67.53 90 top
R12  60.25,52.3 270 top
RN1  57.71,39.91 180 top
RN2  53.27,39.91 180 top
RN3  5.96,79.6 0 top
SPEAKER  22.15,24.35 0 top
USB  9.45,92.62 0 top

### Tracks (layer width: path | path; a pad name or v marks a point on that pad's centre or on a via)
+1V2
  Top 0.406: IC1.5 11.35,4.35 C6.1 13.42,2.93 IC4.3
+3V3  (via drill 0.3)
  Top 0.254: IC8.108 29.28,51.17 29.14,51.03 29.14,50.23 28.34,49.44 28.18,49.44 C28.1 27.55,48.8 v26.44,48.8 | IC8.84 27.3,63.17 C26.1 v25.17,62.46 v25.17,62.45 | IC8.95 28.95,57.67 27.87,56.58 27.7,56.58 C27.1 v25.8,56.11 | IC8.144 IC8.143 49.13,46.89 C35.1 49.14,46.9 v50.25,46.9 | IC8.131 43.13,47.19 C29.1 v43.74,45.15 | IC8.121 38.13,47.58 C30.1 v39.13,45.15 v39.14,45.15 | IC8.30 50.53,65.67 50.25,65.95 50.25,66.42 50.49,66.67 IC8.32 IC8.33 53.53,67.17 C18.1 v53.9,68.96 | IC8.17 53.15,59.17 C25.1 v53.9,61.34 | v53.9,68.96 | v53.9,61.34 | IC8.6 53.33,53.67 C20.1 v53.9,51.66 | v53.9,51.66 | v50.25,46.9 | IC3.2 4.69,67.29 C3.1 v4.69,68.49 | v4.69,68.49 | IC3.16 5.81,56.09 5.16,56.74 5,56.74 C2.1 | IC3.14 5.33,57.69 C2.1 | C2.1 v4.69,58.49 | C1.1 v4.69,51.66 | C1.1 | IC3.23 4.95,50.49 C1.1 | IC3.50 19.98,64.89 C5.1 20.56,65.47 v21.67,65.47 | IC3.29 20.01,48.09 C4.1 v21.51,48.17 v21.52,48.17 | IC8.39 48.63,72.81 C31.1 48.5,74.2 v48.5,75 | IC8.52 42.13,72.95 C32.1 v41.52,75 | IC8.62 37.13,72.88 C33.1 v36.44,75 | IC8.72 32.13,71.52 31.36,72.3 30.88,72.3 30.09,73.09 30.09,73.25 C34.1 29.14,74.2 v29.14,75 | v29.14,75 | R12.2 60.25,49.91 v59.14,49.91 | R11.2 v58.5,69.92 | v28.02,100.87 29.02,100.87 Q1.1 29.12,100.87 30.42,100.87 Q1.4
  Top 0.406: v5.64,8 C7.1 5.64,6.89 IC1.3 7.55,7.84 7.86,8.16 9.13,8.16 9.45,7.84 IC1.1
  pour Route15: -2.3,-14.38 -2.3,110.08 72.95,110.08 72.95,-14.38
+5V  (via drill 0.3)
  Top 0.406: IC7.8 59.93,23.72 59.46,24.2 59.46,25.15 | 59.46,25.15 C11.1 | IC6.6 48.8,34.49 48.66,34.36 48.66,33.89 C9.+ 48.67,33.88 v47.23,33.88 | v60.57,25.31 59.46,25.31 59.46,25.15 | IC5.6 59.3,4.99 C10.1 v63.74,7.53 | PWR.2 27.55,15.47 25.96,13.88 18.02,13.88 0.88,31.02 v0.88,63.41 | v7.23,69.76 12.94,69.76 14.21,71.03 14.21,73.57 13.26,74.52 IC2.5
  Bottom 0.406: v0.88,63.41 v7.23,69.76
  Bottom 0.813: PWR.2 50.72,17.37 63.74,17.37 | 63.74,17.37 v63.74,7.53 | 63.74,17.37 63.74,25.31 | 63.74,25.31 v60.57,25.31 | 63.74,25.31 63.74,31.66 61.52,33.88 v47.23,33.88
A0  (via drill 0.3)
  Top 0.254: IC8.10 50.6,55.67 v49.3,54.36 | IC3.11 9.27,60.09 v9.45,59.92
  Bottom 0.254: v49.3,54.36 46.76,54.36 45.33,55.79 38.98,55.79 36.75,53.56 17.23,53.56 10.88,59.92 v9.45,59.92
A1  (via drill 0.3)
  Top 0.254: IC8.11 50.47,56.17 49.3,54.99 v48.66,54.99 | IC3.10 9.27,60.89 v9.45,60.71
  Bottom 0.254: v48.66,54.99 46.76,54.99 45.49,56.26 38.82,56.26 36.6,54.04 17.39,54.04 10.72,60.71 v9.45,60.71
A2  (via drill 0.3)
  Top 0.254: IC8.12 50.02,56.67 49.14,55.79 v48.66,55.79 | IC3.9 9.26,61.69 v9.45,61.5
  Bottom 0.254: v48.66,55.79 46.6,55.79 45.64,56.74 38.66,56.74 36.44,54.52 17.55,54.52 10.56,61.5 v9.45,61.5
A3  (via drill 0.3)
  Top 0.254: IC8.13 49.56,57.17 48.98,56.58 v48.66,56.58 | IC3.8 9.25,62.49 v9.45,62.3
  Bottom 0.254: v48.66,56.58 46.44,56.58 45.8,57.22 38.5,57.22 36.28,54.99 17.7,54.99 10.4,62.3 v9.45,62.3
A4  (via drill 0.3)
  Top 0.254: IC8.14 49.27,57.67 48.98,57.38 v48.66,57.38 | IC3.7 9.25,63.29 v9.45,63.09
  Bottom 0.254: v48.66,57.38 47.23,57.38 46.92,57.69 38.34,57.69 36.12,55.47 17.86,55.47 10.24,63.09 v9.45,63.09
A5  (via drill 0.3)
  Top 0.254: IC8.15 v48.67,58.17 v48.66,58.17 | v21.04,56.11 21.36,56.11 22.15,56.9 22.15,60.71 19.57,63.29 IC3.48
  Bottom 0.254: v48.66,58.17 38.18,58.17 36.12,56.11 32.15,56.11 31.36,56.9 22.15,56.9 21.36,56.11 v21.04,56.11
A6  (via drill 0.3)
  Top 0.254: IC8.50 43.13,69.47 42.15,68.49 42.15,63.72 v41.83,63.41 | v20.4,56.74 21.36,56.74 21.67,57.06 21.67,60.55 19.73,62.49 IC3.47
  Bottom 0.254: v41.83,63.41 40.88,62.45 40.88,62.14 36.12,57.38 21.99,57.38 21.36,56.74 v20.4,56.74
A7  (via drill 0.3)
  Top 0.254: IC8.53 41.63,64.47 v41.2,64.04 | v21.04,57.38 21.04,58.64 21.2,58.8 21.2,60.39 19.9,61.69 IC3.46
  Bottom 0.254: v41.2,64.04 40.41,63.25 40.41,62.3 35.96,57.85 21.99,57.85 21.52,57.85 v21.04,57.38
A8  (via drill 0.3)
  Top 0.254: IC8.54 41.13,65.25 v40.56,64.68 | v20.4,58.01 20.4,58.8 20.72,59.12 20.72,60.23 20.06,60.89 IC3.45
  Bottom 0.254: v40.56,64.68 39.93,64.04 39.93,62.45 35.8,58.33 21.36,58.33 21.04,58.01 v20.4,58.01
A9  (via drill 0.3)
  Top 0.254: IC8.55 40.63,66.02 v39.93,65.31 | IC3.44 17.25,60.09 16.91,59.76 v16.91,59.28
  Bottom 0.254: v39.93,65.31 39.45,64.84 39.45,62.61 35.64,58.8 21.2,58.8 21.04,58.64 17.55,58.64 v16.91,59.28
A10  (via drill 0.3)
  Top 0.254: IC8.56 40.13,66.78 v39.3,65.95 | IC3.38 18.96,55.29 19.29,55.63 19.29,58.64 v19.29,59.76
  Bottom 0.254: v39.3,65.95 38.98,65.63 38.98,62.77 35.48,59.28 21.04,59.28 20.88,59.12 19.77,59.12 19.29,59.6 v19.29,59.76
A11  (via drill 0.3)
  Top 0.254: IC8.57 39.63,67.56 v38.66,66.58 | IC3.37 19.11,54.49 19.77,55.15 19.77,58.96 20.09,59.28 v20.09,59.76 | v20.09,59.76
  Bottom 0.254: v38.66,66.58 38.5,66.42 38.5,62.93 35.33,59.76 v20.09,59.76
A12
  Top 0.254: IC8.87 28.98,61.67 27.87,60.55 24.69,60.55 22.63,58.49 22.63,56.74 19.58,53.69 IC3.36
A13
  Top 0.254: IC8.88 29.11,61.17 28.02,60.07 24.85,60.07 23.1,58.33 23.1,56.58 19.41,52.89 IC3.35
A14
  Top 0.254: IC8.89 29.25,60.67 28.18,59.6 25.01,59.6 23.58,58.17 23.58,56.42 19.25,52.09 IC3.34
A15  (via drill 0.3)
  Top 0.254: IC8.90 29.39,60.17 28.34,59.12 25.17,59.12 24.05,58.01 24.05,56.26 22.78,54.99 | IC3.21 7.08,51.98 v12.47,51.98 | 22.78,54.99 | v19.13,51.34 22.78,54.99
  Bottom 0.254: v12.47,51.98 15.48,51.98 16.12,51.34 v19.13,51.34
A16  (via drill 0.3)
  Top 0.254: IC8.80 28.97,65.17 27.71,66.42 24.69,66.42 22.94,64.68 v22.78,64.68 | IC3.20 10.84,52.89 12.62,54.68 12.62,60.87 15.8,64.04 v15.8,64.68
  Bottom 0.254: v22.78,64.68 22.47,64.36 16.12,64.36 v15.8,64.68
A17  (via drill 0.3)
  Top 0.254: IC8.81 28.83,64.67 27.55,65.95 24.85,65.95 23.9,65 v23.9,64.68 | IC3.19 11.01,53.69 12.15,54.83 12.15,61.03 14.85,63.72 v14.85,64.68
  Bottom 0.254: v23.9,64.68 23.74,64.68 22.94,63.88 15.64,63.88 v14.85,64.68
A18  (via drill 0.3)
  Top 0.254: IC8.82 28.7,64.17 27.39,65.47 25.64,65.47 25.01,65.47 24.53,65 24.53,64.36 v23.9,63.72 | IC3.18 11.17,54.49 11.67,54.99 11.67,61.19 13.9,63.41 v13.9,64.68
  Bottom 0.254: v23.9,63.72 23.42,63.72 23.1,63.41 15.16,63.41 v13.9,64.68
A19  (via drill 0.3)
  Top 0.254: IC8.2 48.81,51.67 v48.19,52.3 | IC3.17 6.98,55.31 v9.45,55.31
  Bottom 0.254: v48.19,52.3 | v48.19,52.3 48.82,51.66 48.82,50.87 47.07,49.12 35.8,49.12 | 35.8,49.12 34.22,49.12 32.31,47.22 25.64,47.22 24.05,48.8 13.42,48.8 10.88,51.34 10.88,54.99 10.56,55.31 v9.45,55.31 | 35.8,49.12 35.8,45.31 37.07,44.04 37.07,5.62 40.56,2.13 41.32,2.13 IC4.14
AUDIO-CS
  Top 0.254: IC8.135 45.13,48.05 45.49,47.69 | 45.49,47.69 | 45.49,47.69 45.64,47.53 45.64,45.63 46.6,44.67 54.69,44.67 58.03,41.34 58.03,40.67 RN1.2
CAM-D0  (via drill 0.3)
  Top 0.254: IC8.101 33.25,54.67 34.53,55.95 34.53,62.45 33.58,63.41 v33.58,64.2 | v33.9,77.38 33.9,77.69 32.79,78.81 32.79,89.92 31.36,91.35 v27.23,91.35
  Bottom 0.254: v33.58,64.2 33.58,66.9 32.94,67.53 32.94,76.11 33.9,77.06 v33.9,77.38 | CAM.16 27.23,95.16 v27.23,91.35
CAM-D1  (via drill 0.3)
  Top 0.254: IC8.97 31.59,56.67 32.15,56.11 32.79,56.11 33.1,56.42 33.1,61.98 31.67,63.41 v31.67,64.84 | v31.04,77.38 31.04,77.69 29.77,78.97 29.77,89.44 v28.5,90.71
  Bottom 0.254: v31.67,64.84 31.67,66.9 31.52,67.06 31.52,76.42 31.04,76.9 v31.04,77.38 | v28.5,90.71 CAM.15
CAM-D2  (via drill 0.3)
  Top 0.254: IC8.98 31.46,56.17 31.99,55.63 32.94,55.63 33.58,56.26 33.58,62.14 32.31,63.41 v32.31,64.2 | v31.99,77.38 31.99,77.54 30.25,79.28 30.25,90.24 v29.77,90.71
  Bottom 0.254: v32.31,64.2 32.31,65.95 32.31,66.9 31.99,67.22 v31.99,77.38 | CAM.14 29.77,95.16 v29.77,90.71
CAM-D3  (via drill 0.3)
  Top 0.254: IC8.99 31.32,55.67 31.83,55.15 33.1,55.15 34.06,56.11 34.06,62.3 32.94,63.41 v32.94,64.84 | v33.1,77.38 32.31,78.17 32.31,89.44 v31.04,90.71
  Bottom 0.254: v32.94,64.84 32.94,66.9 32.47,67.38 32.47,76.74 v33.1,77.38 | v31.04,90.71 CAM.13
CAM-D4  (via drill 0.3)
  Top 0.254: IC8.3 49.27,52.17 46.76,54.68 46.76,61.34 v46.12,62.14
  Bottom 0.254: v46.12,62.14 45.96,62.14 43.9,64.2 43.9,73.09 42.95,74.04 42.95,84.68 40.41,87.22 38.34,87.22 34.85,90.71 34.85,95.16 CAM.12 | v46.12,62.14
CAM-D5  (via drill 0.3)
  Top 0.254: v45.49,61.5 45.49,59.12 45.49,54.36 45.49,50.71 45.64,50.55 45.64,49.33 IC8.136
  Bottom 0.254: v45.49,61.5 45.49,61.98 44.06,63.41 43.42,64.04 43.42,72.93 42.47,73.89 42.47,84.52 40.41,86.58 38.34,86.58 33.58,91.35 CAM.11
CAM-D6  (via drill 0.3)
  Top 0.254: IC8.4 49.4,52.67 47.39,54.68 v47.39,61.5 | CAM.10 37.39,95.16 37.39,93.25 38.03,92.62 38.03,88.49 v38.66,87.86
  Bottom 0.254: v47.39,61.5 47.39,61.82 46.44,62.77 45.96,62.77 44.38,64.36 44.38,72.61 45.01,73.25 45.01,84.52 41.68,87.86 v38.66,87.86
CAM-D7  (via drill 0.3)
  Top 0.254: IC8.5 49.54,53.17 48.03,54.68 48.03,57.85 48.03,59.44 v48.03,62.14
  Bottom 0.254: v48.03,62.14 47.71,62.14 46.6,63.25 46.12,63.25 44.85,64.52 44.85,72.46 45.49,73.09 45.49,84.68 41.68,88.49 38.66,88.49 36.12,91.03 CAM.9
CAM-FSIN  (via drill 0.3)
  Top 0.254: IC8.41 47.63,69.2 46.76,68.33 v46.44,68.33 | CAM.19 | CAM.19 25.33,91.98 36.75,91.98 v36.75,91.67 | v36.75,91.67
  Bottom 0.254: v46.44,68.33 46.12,68.33 45.33,69.12 45.33,72.3 46.76,73.73 47.07,73.73 47.39,74.04 47.39,85.16 43.58,88.97 38.82,88.97 36.75,91.03 v36.75,91.67
CAM-HSYNC  (via drill 0.3)
  Top 0.254: IC8.40 48.13,71.72 v47.71,72.14 | CAM.6 39.93,95.16 v39.93,90.71
  Bottom 0.254: v47.71,72.14 49.61,72.14 50.57,73.09 50.57,85.47 45.33,90.71 v39.93,90.71
CAM-LED0  (via drill 0.3)
  Top 0.254: IC8.28 50.55,64.67 50.25,64.36 50.25,64.04 v49.93,63.72 | v59.3,57.38 59.46,57.38 LED2.C
  Bottom 0.254: v49.93,63.72 49.93,62.77 52.95,59.76 56.92,59.76 v59.3,57.38
CAM-LED1  (via drill 0.3)
  Top 0.254: IC8.29 50.26,65.17 49.14,64.04 v49.14,63.72 | LED1.C 60.57,66.42 59.77,65.63 | 59.77,65.63 | 59.77,65.63 59.61,65.47 58.5,65.47 v58.03,65
  Bottom 0.254: v49.14,63.72 49.14,64.04 50.09,65 v58.03,65
CAM-PCLK  (via drill 0.3)
  Top 0.254: IC8.42 47.13,71.44 46.76,71.82 v46.44,71.82 | v38.66,90.71 CAM.7
  Bottom 0.254: v38.66,90.71 39.3,90.08 45.33,90.08 50.09,85.31 50.09,73.25 49.61,72.77 47.23,72.77 46.44,71.98 v46.44,71.82
CAM-PWDN  (via drill 0.3)
  Top 0.254: IC8.43 46.63,69.32 v46.44,69.12 | CAM.20 24.69,95.16 24.69,93.25 25.33,92.62 37.07,92.62 v37.39,92.3
  Bottom 0.254: v46.44,69.12 46.44,70.23 45.8,70.87 45.8,72.14 46.92,73.25 47.23,73.25 47.87,73.89 47.87,85.31 43.74,89.44 38.98,89.44 37.39,91.03 v37.39,92.3
CAM-VSYNC  (via drill 0.3)
  Top 0.254: IC8.137 46.13,54.35 46.12,54.52 46.12,58.96 46.12,59.44 v46.12,60.87 | v41.2,91.35 CAM.5
  Bottom 0.254: v46.12,60.87 47.71,60.87 48.66,61.82 48.66,62.45 47.39,63.72 46.28,63.72 45.33,64.68 45.33,65.31 46.92,66.9 46.92,67.53 52.63,73.25 52.63,85 46.28,91.35 v41.2,91.35
CAM-XCLK
  Top 0.254: CAM.8 37.39,97.7 37.39,99.28 36.75,99.92 32.31,99.92 31.67,99.28 30.73,99.28 Q1.3
D0  (via drill 0.3)
  Top 0.254: IC3.22 12.73,51.29 13.1,51.66 13.1,60.71 14.21,61.82 v14.53,61.82 | IC8.85 28.23,62.67 v28.02,62.45 | v30.72,50.23 30.72,43.72 34.22,40.23 v40.25,40.23
  Route2 0.254: v28.02,62.45 28.18,62.45 30.72,59.92 v30.72,50.23
  Bottom 0.254: v14.53,61.82 15.48,61.82 15.8,61.5 18.18,61.5 18.5,61.82 27.07,61.82 27.71,62.45 v28.02,62.45 | v40.25,40.23 40.25,6.26 41.52,4.99 51.16,4.99 IC4.19
D1  (via drill 0.3)
  Top 0.254: IC3.24 11.77,49.69 13.58,51.5 13.58,60.55 14.21,61.19 v15.16,61.19 | IC8.86 28.69,62.17 28.18,61.66 v28.02,61.66 | v29.93,50.23 29.93,43.88 34.22,39.59 v40.88,39.59
  Route2 0.254: v28.02,61.66 29.93,59.76 v29.93,50.23
  Bottom 0.254: v15.16,61.19 15.32,61.03 18.34,61.03 18.66,61.34 27.71,61.34 v28.02,61.66 | v40.88,39.59 40.88,6.57 41.83,5.62 51.68,5.62 53.9,3.4 55.29,3.4 IC4.20
D2  (via drill 0.3)
  Top 0.254: IC3.25 7.93,48.89 v8.34,48.48 | v33.9,46.26 33.9,47.22 34.63,47.95 IC8.114
  Bottom 0.254: v33.9,46.26 8.81,46.26 8.34,46.74 v8.34,48.48 IC4.21
D3  (via drill 0.3)
  Top 0.254: IC3.27 8.9,47.29 v9.29,46.9 | IC8.115 35.13,47.5 v34.53,46.9
  Bottom 0.254: v34.53,46.9 32.63,46.9 32.47,46.74 9.45,46.74 v9.29,46.9 9.29,54.36 8.81,54.83 8.81,65.31 10.88,67.38 IC4.22
D4  (via drill 0.3)
  Top 0.254: IC8.58 39.13,68.33 v38.66,67.85 | IC3.28 17.15,47.29 14.05,50.39 14.05,59.6 14.21,59.76 v14.21,60.07
  Bottom 0.254: v38.66,67.85 38.66,67.53 38.03,66.9 38.03,63.09 35.17,60.23 30.72,60.23 30.56,60.39 18.98,60.39 18.66,60.07 15.8,60.07 15.48,59.76 14.85,59.76 14.53,60.07 v14.21,60.07 14.21,60.39 13.42,61.19 13.42,62.3 11.83,63.88 11.83,67.69 13.42,69.28 IC4.23
D5  (via drill 0.3)
  Top 0.254: IC8.59 38.63,69.09 v38.03,68.49 | IC3.30 16.98,48.89 14.53,51.34 14.53,59.44 15.16,60.07 v15.16,60.39
  Bottom 0.254: v38.03,68.49 38.03,67.53 37.55,67.06 37.55,63.25 35.01,60.71 30.88,60.71 30.72,60.87 18.82,60.87 18.5,60.55 15.32,60.55 | v15.16,60.39 15.32,60.55 | 15.32,60.55 14.69,60.55 13.9,61.34 13.9,62.45 12.31,64.04 12.31,66.74 12.31,67.53 15.96,71.19 IC4.24
D6  (via drill 0.3)
  Top 0.254: IC8.60 38.13,69.55 37.71,69.12 v37.39,69.12 | IC3.31 16.81,49.69 15.01,51.5 15.01,59.28 16.12,60.39 v16.12,62.14
  Bottom 0.254: v37.39,69.12 37.39,67.53 37.07,67.22 37.07,63.41 34.85,61.19 31.2,61.19 29.14,63.25 25.01,63.25 24.37,62.61 23.58,62.61 23.26,62.3 18.34,62.3 18.18,62.14 v16.12,62.14 15.8,62.45 14.53,62.45 12.78,64.2 12.78,67.38 18.5,73.09 IC4.25
D7  (via drill 0.3)
  Top 0.254: IC8.63 36.63,68.61 v36.75,68.49 | IC3.33 16.33,51.29 15.48,52.14 15.48,59.12 16.75,60.39 v16.75,62.77
  Bottom 0.254: v36.75,68.49 36.75,67.53 36.6,67.38 36.6,63.57 34.69,61.66 31.36,61.66 29.29,63.72 24.85,63.72 24.21,63.09 23.42,63.09 23.1,62.77 v16.75,62.77 16.59,62.93 14.69,62.93 13.26,64.36 13.26,66.74 | IC4.26 21.04,75 13.26,67.22 13.26,66.74 | 13.26,66.74
D8  (via drill 0.3)
  Top 0.254: IC8.64 36.13,67.86 v36.12,67.85 | IC3.49 17.18,64.09 16.75,64.52 v16.75,65.31
  Bottom 0.254: v36.12,67.85 36.12,63.72 34.53,62.14 31.52,62.14 28.34,65.31 22.47,65.31 21.99,64.84 17.23,64.84 v16.75,65.31 15.48,65.31 15.16,65.63 15.16,68.49 23.58,76.9 IC4.27
D9  (via drill 0.3)
  Top 0.254: IC8.65 35.63,68.32 v35.17,67.85 | IC3.51 17.33,65.69 17.07,65.95 v16.12,65.95
  Bottom 0.254: v35.17,67.85 35.64,67.38 35.64,63.88 34.37,62.61 31.67,62.61 28.5,65.79 22.63,65.79 22.31,66.11 21.36,66.11 21.2,65.95 v16.12,65.95 15.96,65.95 15.64,66.27 15.64,66.74 | v35.17,67.85 | IC4.28 26.12,78.81 15.64,68.33 15.64,66.74 | 15.64,66.74
D10  (via drill 0.3)
  Top 0.254: IC8.66 35.13,68.77 v34.22,67.85 | IC3.52 17.88,66.58 v16.75,66.58
  Bottom 0.254: v34.22,67.85 34.22,67.53 35.17,66.58 35.17,64.04 34.22,63.09 31.83,63.09 28.66,66.27 22.78,66.27 22.47,66.58 v16.75,66.58 16.28,66.58 16.12,66.74 16.12,68.17 28.66,80.71 IC4.29
D11  (via drill 0.3)
  Top 0.254: IC8.67 34.63,69.38 33.74,68.49 v33.58,68.49 | IC3.54 16.99,68.09 v16.75,67.85
  Bottom 0.254: v33.58,68.49 33.58,67.53 34.69,66.42 34.69,64.2 34.06,63.57 31.99,63.57 28.82,66.74 23.26,66.74 21.83,68.17 | v16.75,67.85 17.07,68.17 21.83,68.17 | IC4.30 31.2,81.82 21.83,72.46 21.83,68.17
D12  (via drill 0.3)
  Top 0.254: IC8.68 34.13,69.52 33.74,69.12 31.67,69.12 31.04,69.76 v24.37,69.76 22.15,69.76 | 22.15,69.76 21.67,70.23 16.28,70.23 14.05,68.01 7.05,68.01 IC3.1 | 22.15,69.76
  Bottom 0.254: v24.37,69.76 24.37,74.36 33.74,83.73 IC4.31
D13  (via drill 0.3)
  Top 0.254: IC8.77 29.37,66.67 26.91,69.12 v25.01,69.12 22.15,69.12 21.52,69.76 16.44,69.76 13.1,66.42 7.03,66.42 IC3.3
  Bottom 0.254: v25.01,69.12 25.01,74.36 29.61,78.97 31.16,78.97 IC4.32
D14  (via drill 0.3)
  Top 0.254: IC8.78 29.23,66.17 28.02,67.38 26.91,68.49 v25.64,68.49 22.15,68.49 21.36,69.28 16.59,69.28 12.94,65.63 7.03,65.63 IC3.4
  Bottom 0.254: v25.64,68.49 25.64,74.36 29.77,78.49 33.22,78.49 IC4.33
D15  (via drill 0.3)
  Top 0.254: IC8.79 29.1,65.67 26.91,67.85 v26.28,67.85 22.15,67.85 21.2,68.81 16.75,68.81 12.04,64.09 IC3.6
  Bottom 0.254: v26.28,67.85 26.28,74.36 29.93,78.01 35.28,78.01 IC4.34
EXT1  (via drill 0.3)
  Top 0.254: IC8.75 29.32,67.67 v28.82,68.17 | v30.25,77.38 27.55,80.08 v27.55,90.08
  Bottom 0.254: EXT.1 32.31,97.38 32.31,91.03 31.36,90.08 v27.55,90.08 | v28.82,68.17 31.04,70.39 31.04,76.11 30.25,76.9 v30.25,77.38
EXT2  (via drill 0.3)
  Top 0.254: IC8.46 45.13,72.58 46.76,74.2 46.76,75 48.03,76.27 48.03,95.32 v49.45,96.75
  Bottom 0.254: EXT.2 34.85,99.92 46.92,99.92 47.55,99.28 47.55,98.02 48.82,96.75 v49.45,96.75
EXT3
  Top 0.254: IC8.48 44.13,72.21 46.28,74.36 46.28,75.16 47.55,76.42 47.55,99.28 46.92,99.92 42.47,99.92 EXT.7
FSMC_NBL0  (via drill 0.3)
  Top 0.254: IC8.141 48.13,50.44 v47.23,51.34 | IC3.39 17.22,56.09 16.91,55.79 v16.91,52.45
  Bottom 0.254: v16.91,52.45 17.07,52.61 37.07,52.61 39.3,54.83 43.74,54.83 v47.23,51.34
FSMC_NBL1  (via drill 0.3)
  Top 0.254: IC8.142 48.63,50.89 v48.19,51.34 | IC3.12 9.28,59.29 v9.45,59.12
  Bottom 0.254: v48.19,51.34 44.22,55.31 39.14,55.31 36.91,53.09 17.07,53.09 11.2,58.96 11.04,59.12 v9.45,59.12
FSMC_NE2  (via drill 0.3)
  Top 0.254: IC8.124 39.63,50.69 v39.61,50.71 | IC3.13 9.28,58.49 v9.45,58.33
  Bottom 0.254: v39.61,50.71 39.14,51.18 | 39.14,51.18 | 39.14,51.18 38.98,51.34 37.39,51.34 37.07,51.03 37.07,50.39 36.75,50.07 33.9,50.07 31.99,48.17 25.96,48.17 23.42,50.71 12.78,50.71 11.83,51.66 11.83,56.58 10.09,58.33 v9.45,58.33
FSMC_NOE  (via drill 0.3)
  Top 0.254: v36.44,50.71 36.63,50.51 IC8.118 36.63,48.36 36.44,48.17 35.8,48.17 35.64,48.01 35.64,45.15 37.07,43.72 v37.71,43.72 | IC3.42 16.76,58.49 16.12,57.85 16.12,57.69 | v16.12,52.45 16.12,57.69 | 16.12,57.69 16.12,57.85
  Bottom 0.254: v36.44,50.71 35.01,52.14 18.5,52.14 17.86,52.14 17.55,52.14 17.23,51.82 16.59,51.82 16.12,52.3 v16.12,52.45 | v37.71,43.72 37.71,5.94 40.56,3.08 42.9,3.08 IC4.15
FSMC_NWE  (via drill 0.3)
  Top 0.254: v37.71,50.71 37.39,50.71 37.13,50.45 IC8.119 37.13,48.23 36.6,47.69 36.28,47.69 36.12,47.53 36.12,45.31 36.28,45.15 37.07,44.36 v38.34,44.36 | IC3.15 v9.45,56.9
  Bottom 0.254: v37.71,50.71 37.71,50.39 36.91,49.6 34.06,49.6 32.15,47.69 25.8,47.69 24.21,49.28 13.58,49.28 11.35,51.5 11.35,56.11 10.56,56.9 v9.45,56.9 | v38.34,44.36 38.34,6.26 40.88,3.72 44.81,3.72 IC4.16
GND  (via drill 0.3)
  Top 0.254: IC8.107 28.51,51.67 C28.2 25.65,51.02 | C24.2 25.65,51.02 | 25.65,51.02 25.64,51.02 v25.64,49.6 | IC8.83 27.29,63.67 C26.2 v25.17,64.36 | IC8.94 27.39,58.17 C27.2 26.44,58.01 24.85,56.42 v24.85,56.11 | IC8.138 46.63,46.86 C35.2 v46.92,45.31 | IC8.130 42.63,47.38 C29.2 v41.84,45.15 v41.83,45.15 | IC8.120 37.63,47.3 C30.2 v37.23,45.15 | C21.2 | C21.2 v57.71,49.91 | IC8.16 53.25,58.67 C25.2 v53.9,56.58 | v53.9,64.2 C18.2 53.37,66.17 IC8.31 | v53.9,64.2 | C19.2 v56.12,68.96 | C22.2 59.3,63.72 v59.3,64.84 | v53.9,56.58 | v53.9,56.58 C20.2 | v53.9,56.58 | IC3.41 v16.91,57.69 | IC3.5 4.69,64.89 C3.2 v4.69,63.72 | v4.69,63.72 | v4.69,53.72 C2.2 | C2.2 | IC3.26 4.92,48.09 C1.2 v4.69,46.9 | v4.69,46.9 | IC3.53 20.33,67.29 C5.2 v21.67,67.22 | IC3.32 19.66,50.49 C4.2 v21.52,50.07 | IC8.38 49.13,72.93 C31.2 49.45,73.57 v49.45,75 | IC8.51 42.63,72.78 C32.2 43.74,73.89 43.74,74.36 v43.74,75 | IC8.61 37.63,72.86 C33.2 v38.34,75 | v30.25,75 31.04,75 C23.2 C34.2 | v28.02,98.97 29.02,98.97 Q1.2 | v12.31,70.87 R1.1 | IC2.2 11.35,76.27 v11.83,75.79 | C8.2
  Top 0.406: IC1.2 8.5,5.62 7.23,5.62 6.28,4.67 C7.2 v5.64,3.24 | C6.2 v11.67,8 | IC6.4 50.4,35.79 49.3,36.9 49.3,37.36 C9.- 48.81,37.85 v47.39,37.85 | C17.2 53.58,19.91 IC7.4 58.66,19.91 | 58.66,19.91 IC7.5 | 58.66,19.91 58.66,21.18 | 58.66,21.18 IC7.6 | 58.66,21.18 58.66,23.72 57.71,24.67 57.71,25.31 C11.2 v55.96,25.31 | IC5.2 57.71,11.34 R9.1 | C10.2 IC5.4 | C16.- | C16.- v61.68,29.44 | v58.82,32.29 58.82,33.19 IC6.9
  Top 0.508: v9.13,79.6 C8.2 10.72,79.28 | USB.4 v5.96,85.47
  other vias: 17.07,87.86 1.83,94.36 1.83,87.86 17.07,94.36
  pour Route2: -0.71,-12.79 -0.71,108.81 71.36,108.81 71.36,-12.79
  pour Top: 0.88,94.84 0.88,87.54 2.78,87.54 2.78,94.84
  pour Top: 16.12,94.84 16.12,87.54 18.02,87.54 18.02,94.84
I2C2-SCL
  Top 0.254: IC8.69 33.63,72.03 35.33,73.73 35.33,75 37.87,77.54 37.87,85.31 43.74,91.19 CAM.3
I2C2-SDA
  Top 0.254: IC8.70 33.13,72.17 34.85,73.89 34.85,75.16 37.39,77.69 37.39,85.47 42.47,90.55 42.47,95.16 CAM.4
I2S2-CK  (via drill 0.3)
  Top 0.254: IC8.74 32.31,68.17 33.74,66.74 36.6,66.74 37.87,65.47 v41.83,61.5 | RN2.3 52.86,41.27 v52.63,41.5
  Bottom 0.254: v41.83,61.5 43.58,59.76 50.57,59.76 52,58.33 52,44.04 52.95,43.09 52.95,41.82 v52.63,41.5
I2S2-MCK  (via drill 0.3)
  Top 0.254: IC8.96 32.04,57.17 v32.47,56.74 | v58.66,41.5 58.91,41.25 RN1.1
  Bottom 0.254: v32.47,56.74 36.12,56.74 38.18,58.8 50.25,58.8 51.04,58.01 51.04,42.14 52.31,40.87 58.03,40.87 v58.66,41.5
I2S2-SD  (via drill 0.3)
  Top 0.254: IC8.76 32.68,67.17 33.58,66.27 36.12,66.27 v41.83,60.55 | RN2.2 53.67,41.42 v52.31,42.77
  Bottom 0.254: v41.83,60.55 43.11,59.28 50.41,59.28 51.52,58.17 51.52,43.56 v52.31,42.77
I2S2-WS  (via drill 0.3)
  Top 0.254: IC8.73 32.45,68.67 33.9,67.22 37.07,67.22 v41.83,62.45 | RN2.1 54.47,41.89 v53.58,42.77
  Bottom 0.254: v41.83,62.45 44.06,60.23 50.72,60.23 52.47,58.49 52.47,44.2 53.58,43.09 v53.58,42.77
MAIN-RX  (via drill 0.3)
  Top 0.254: v49.3,92.62 49.3,86.11 50.57,84.84 50.57,75.95 51.52,75 51.52,68.7 IC8.36
  Bottom 0.254: EXT.5 39.93,97.38 39.93,93.25 40.56,92.62 v49.3,92.62
MAIN-TX  (via drill 0.3)
  Top 0.254: IC8.37 49.63,71.34 51.04,72.75 51.04,74.84 50.09,75.79 50.09,84.68 48.66,86.11 v48.66,91.98
  Bottom 0.254: EXT.3 37.39,97.38 37.39,93.25 38.66,91.98 v48.66,91.98
N$1
  Top 0.406: 50.57,25.31 50.73,25.31 R7.1 R6.2
N$2
  Top 0.254: USB.2 10.45,85.84 9.77,85.16 9.77,83.41 7.23,80.87 7.16,80.8 RN3.5
N$3
  Top 0.254: USB.3 8.45,86.06 5.32,82.93 4.76,82.37 RN3.8
N$4
  Top 0.254: IC6.2 53.9,37.09 53.9,38.48 53.67,38.72 RN2.7
N$6
  Top 0.254: IC6.3 54.38,36.44 54.38,38.33 54.47,38.41 RN2.8
N$7
  Top 0.254: IC6.1 53.42,37.74 53.42,38.33 52.86,38.88 RN2.6
N$8
  Top 0.254: IC6.16 58.91,37.92 RN1.8
N$9
  Top 0.406: 58.03,3.4 60.57,3.4 IC5.5 | 58.03,3.4 58.03,6.89 C14.1 | 58.03,3.4 53.58,3.4 48.19,8.8 C15.+
N$10
  Top 0.406: C14.2 R9.2
N$11
  Top 0.61: C15.- 40.39,8.48 28.18,8.48 19.02,8.48 SPEAKER.1
N$13
  Top 0.254: IC6.14 57.23,36.44 57.23,39.16 RN1.6
N$14
  Top 0.254: IC6.13 56.76,35.79 56.76,38.33 56.51,38.57 RN1.5
N$15
  Top 0.254: IC6.15 57.71,37.09 57.71,38.33 58.11,38.73 RN1.7
N$16
  Top 0.406: IC6.7 51.8,33.84 50.09,32.13 | 50.09,32.13 | 50.09,32.13 49.93,31.98 46.76,31.98 R4.1
N$17
  Top 0.406: R8.1 R7.2 51.2,23.72 53.1,25.62 C12.1
N$19
  Top 0.406: IC5.3 59.3,15.64 C13.-
N$21
  Top 0.406: IC6.10 55.61,33.84 53.58,31.82 R6.1 55.17,29.44 C16.+
N$22
  Top 0.406: R8.2 51.2,19.59 53.1,21.49 C17.1 53.58,21.18 IC7.3
N$24  (via drill 0.3)
  Top 0.406: C12.2 IC7.1 IC7.2 v57.39,22.45 | C13.+ 56.12,16.1 57.39,17.37 v57.39,18.64
  Bottom 0.406: v57.39,18.64 v57.39,22.45
N$25
  Top 0.406: IC6.8 52.26,33.19 52,32.93 R5.1
N$27
  Top 0.254: IC8.106 26.09,52.17 C24.1
N$28
  Top 0.254: IC8.71 32.63,72.3 33.26,72.93 33.26,75.16 C23.1
N$31
  Top 0.254: IC8.24 56.02,62.67 R10.2
N$32
  Top 0.254: IC8.23 54.35,62.17 55.33,61.19 55.33,57.91 Q2.1 C21.1
N$33
  Top 0.254: R10.1 57.71,60.55 Q2.2 57.71,60.55 58.67,61.5 C22.1
N$35
  Top 0.254: LED2.A 60.57,53.56 R12.1
N$36
  Top 0.254: R11.1 58.67,66.58 60.57,68.49 LED1.A
N$37
  Top 0.406: R4.2 46.44,29.44 48.03,31.02 R6.3 49.62,31.02 R5.2
SPI3-MISO  (via drill 0.3)
  Top 0.254: IC8.112 33.63,48.22 32.79,47.37 32.79,44.2 33.58,43.41 v34.53,43.41
  Bottom 0.254: v34.53,43.41 35.17,42.77 35.17,9.59 31.2,5.62 IC4.10
SPI3-MOSI  (via drill 0.3)
  Top 0.254: IC8.113 34.13,48.08 33.26,47.22 33.26,45.94 v33.9,45.31 | v33.9,41.82 34.69,41.02 38.03,41.02 40.41,43.41 54.22,43.41 56.44,41.18 56.44,40.66 RN1.4
  Bottom 0.254: v33.9,45.31 v33.9,41.82 33.9,9.91 26.12,2.13 IC4.8
SPI3-SCK  (via drill 0.3)
  Top 0.254: IC8.111 33.13,48.36 32.31,47.53 32.31,43.72 33.58,42.45 v34.53,42.45 35.48,41.5 37.71,41.5 40.25,44.04 54.38,44.04 57.23,41.18 57.23,40.66 RN1.3
  Bottom 0.254: v34.53,42.45 34.53,9.75 28.66,3.88 IC4.9
SRST  (via drill 0.3)
  Top 0.254: C19.1 55.49,65 55.49,64.36 54.29,63.17 IC8.25 50.32,63.17 50.09,62.93 v49.14,62.93 | v49.14,62.93
  Bottom 0.254: EXT.11 55.17,89.76 55.17,74.52 47.87,67.22 47.87,65.95 47.23,65.31 47.23,64.68 48.98,62.93 v49.14,62.93
TCK  (via drill 0.3)
  Top 0.254: v49.77,67.53 49.77,65.95 49.45,65.63 44.69,65.63 43.42,64.36 43.42,54.2 41.68,52.45 34.69,52.45 33.42,52.45 32.13,51.17 IC8.109
  Bottom 0.254: EXT.15 57.55,92.46 57.55,75.63 49.77,67.85 v49.77,67.53
TDO-EXT  (via drill 0.3)
  Top 0.254: v47.87,65 47.07,65 44.38,62.3 44.38,50.71 44.13,50.47 IC8.133
  Bottom 0.254: v47.87,65 48.5,65.63 48.5,67.22 55.33,74.04 55.49,74.2 55.65,74.36 55.65,91.82 EXT.13
TDO-M4  (via drill 0.3)
  Top 0.254: v45.96,65 45.96,64.84 43.9,62.77 43.9,54.04 41.83,51.98 33.74,51.98 32.63,50.87 IC8.110
  Bottom 0.254: v45.96,65 47.39,66.42 47.39,67.38 53.11,73.09 53.11,90.87 48.82,95.16 45.64,95.16 45.01,95.79 45.01,97.38 EXT.9
TFT-NE1  (via drill 0.3)
  Top 0.254: IC8.123 39.13,48.33 39.3,48.17 40.09,48.17 40.72,47.53 40.72,45.15 37.71,42.14 v36.44,42.14
  Bottom 0.254: v36.44,42.14 36.44,5.3 38.82,2.92 IC4.13
TFT-RST  (via drill 0.3)
  Top 0.254: IC8.132 43.63,48.12 44.06,47.69 44.69,47.69 45.01,47.37 v45.01,45.15
  Bottom 0.254: v45.01,45.15 44.22,44.36 40.56,44.36 39.61,43.41 39.61,5.94 41.2,4.35 46.71,4.35 IC4.17
TMS  (via drill 0.3)
  Top 0.254: v49.14,66.27 44.69,66.27 42.95,64.52 42.95,54.36 41.52,52.93 33.1,52.93 32.84,52.67 IC8.105
  Bottom 0.254: EXT.17 58.03,94.52 58.03,75.47 50.41,67.85 50.41,67.22 49.45,66.27 v49.14,66.27
TP-CS  (via drill 0.3)
  Top 0.254: IC8.122 38.63,48.04 38.98,47.69 39.93,47.69 40.25,47.37 40.25,45.31 38.03,43.09 v36.44,43.09
  Bottom 0.254: v36.44,43.09 35.8,42.45 35.8,9.43 33.74,7.37 IC4.11
TP-IRQ  (via drill 0.3)
  Top 0.254: IC8.1 50.07,51.17 v49.77,50.87 | v38.98,6.57 28.07,6.57 IC4.7
  Bottom 0.254: v49.77,50.87 47.55,48.64 43.58,48.64 38.98,44.04 v38.98,6.57
TRST  (via drill 0.3)
  Top 0.254: v48.82,64.68 48.5,64.68 48.19,64.36 47.07,64.36 44.85,62.14 44.85,50.55 44.63,50.33 IC8.134
  Bottom 0.254: EXT.19 58.5,96.59 58.5,75.31 50.88,67.69 50.88,66.74 v48.82,64.68
USB-5V
  Top 0.254: USB.1 12.95,87.55 12.94,87.54 | IC2.1
  Top 0.508: IC2.1 C8.1 12.15,79.76 12.15,85.95 12.94,86.74 12.94,87.54 USB.1
USB-DM
  Top 0.254: IC8.103 29.19,53.67 28.66,54.2 23.9,54.2 23.1,53.41 23.1,47.53 20.88,45.31 4.05,45.31 2.47,46.9 2.47,68.81 6.59,72.93 7.16,73.5 RN3.4
USB-DP
  Top 0.254: IC8.104 29.06,53.17 28.5,53.72 24.05,53.72 23.58,53.25 23.58,47.37 21.04,44.83 3.89,44.83 1.99,46.74 1.99,69.28 4.69,71.98 4.76,72.05 RN3.1
USB-EN
  Top 0.254: IC8.100 30.28,55.15 23.58,55.15 22.15,53.72 22.15,47.85 20.56,46.26 4.37,46.26 3.42,47.22 3.42,68.17 6.59,71.34 9.45,71.34 R1.2 IC2.4
USB-FAULT
  Top 0.254: IC8.102 29.33,54.17 28.82,54.68 23.74,54.68 22.63,53.56 22.63,47.69 20.72,45.79 4.21,45.79 2.94,47.06 2.94,68.49 10.4,75.95 IC2.3

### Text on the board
tPlace: Tigers Mannheim | Extension Board v2 | Designed by: A. Ryll | TFT up
tNames: CAM | Pin 1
